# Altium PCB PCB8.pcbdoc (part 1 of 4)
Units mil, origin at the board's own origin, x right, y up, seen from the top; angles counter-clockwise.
Board outline 6799.06 x 5716.8 mil, 2 copper layers (Top Layer, Bottom Layer); 312 components, 374 nets, 1333 pads, 994 vias.
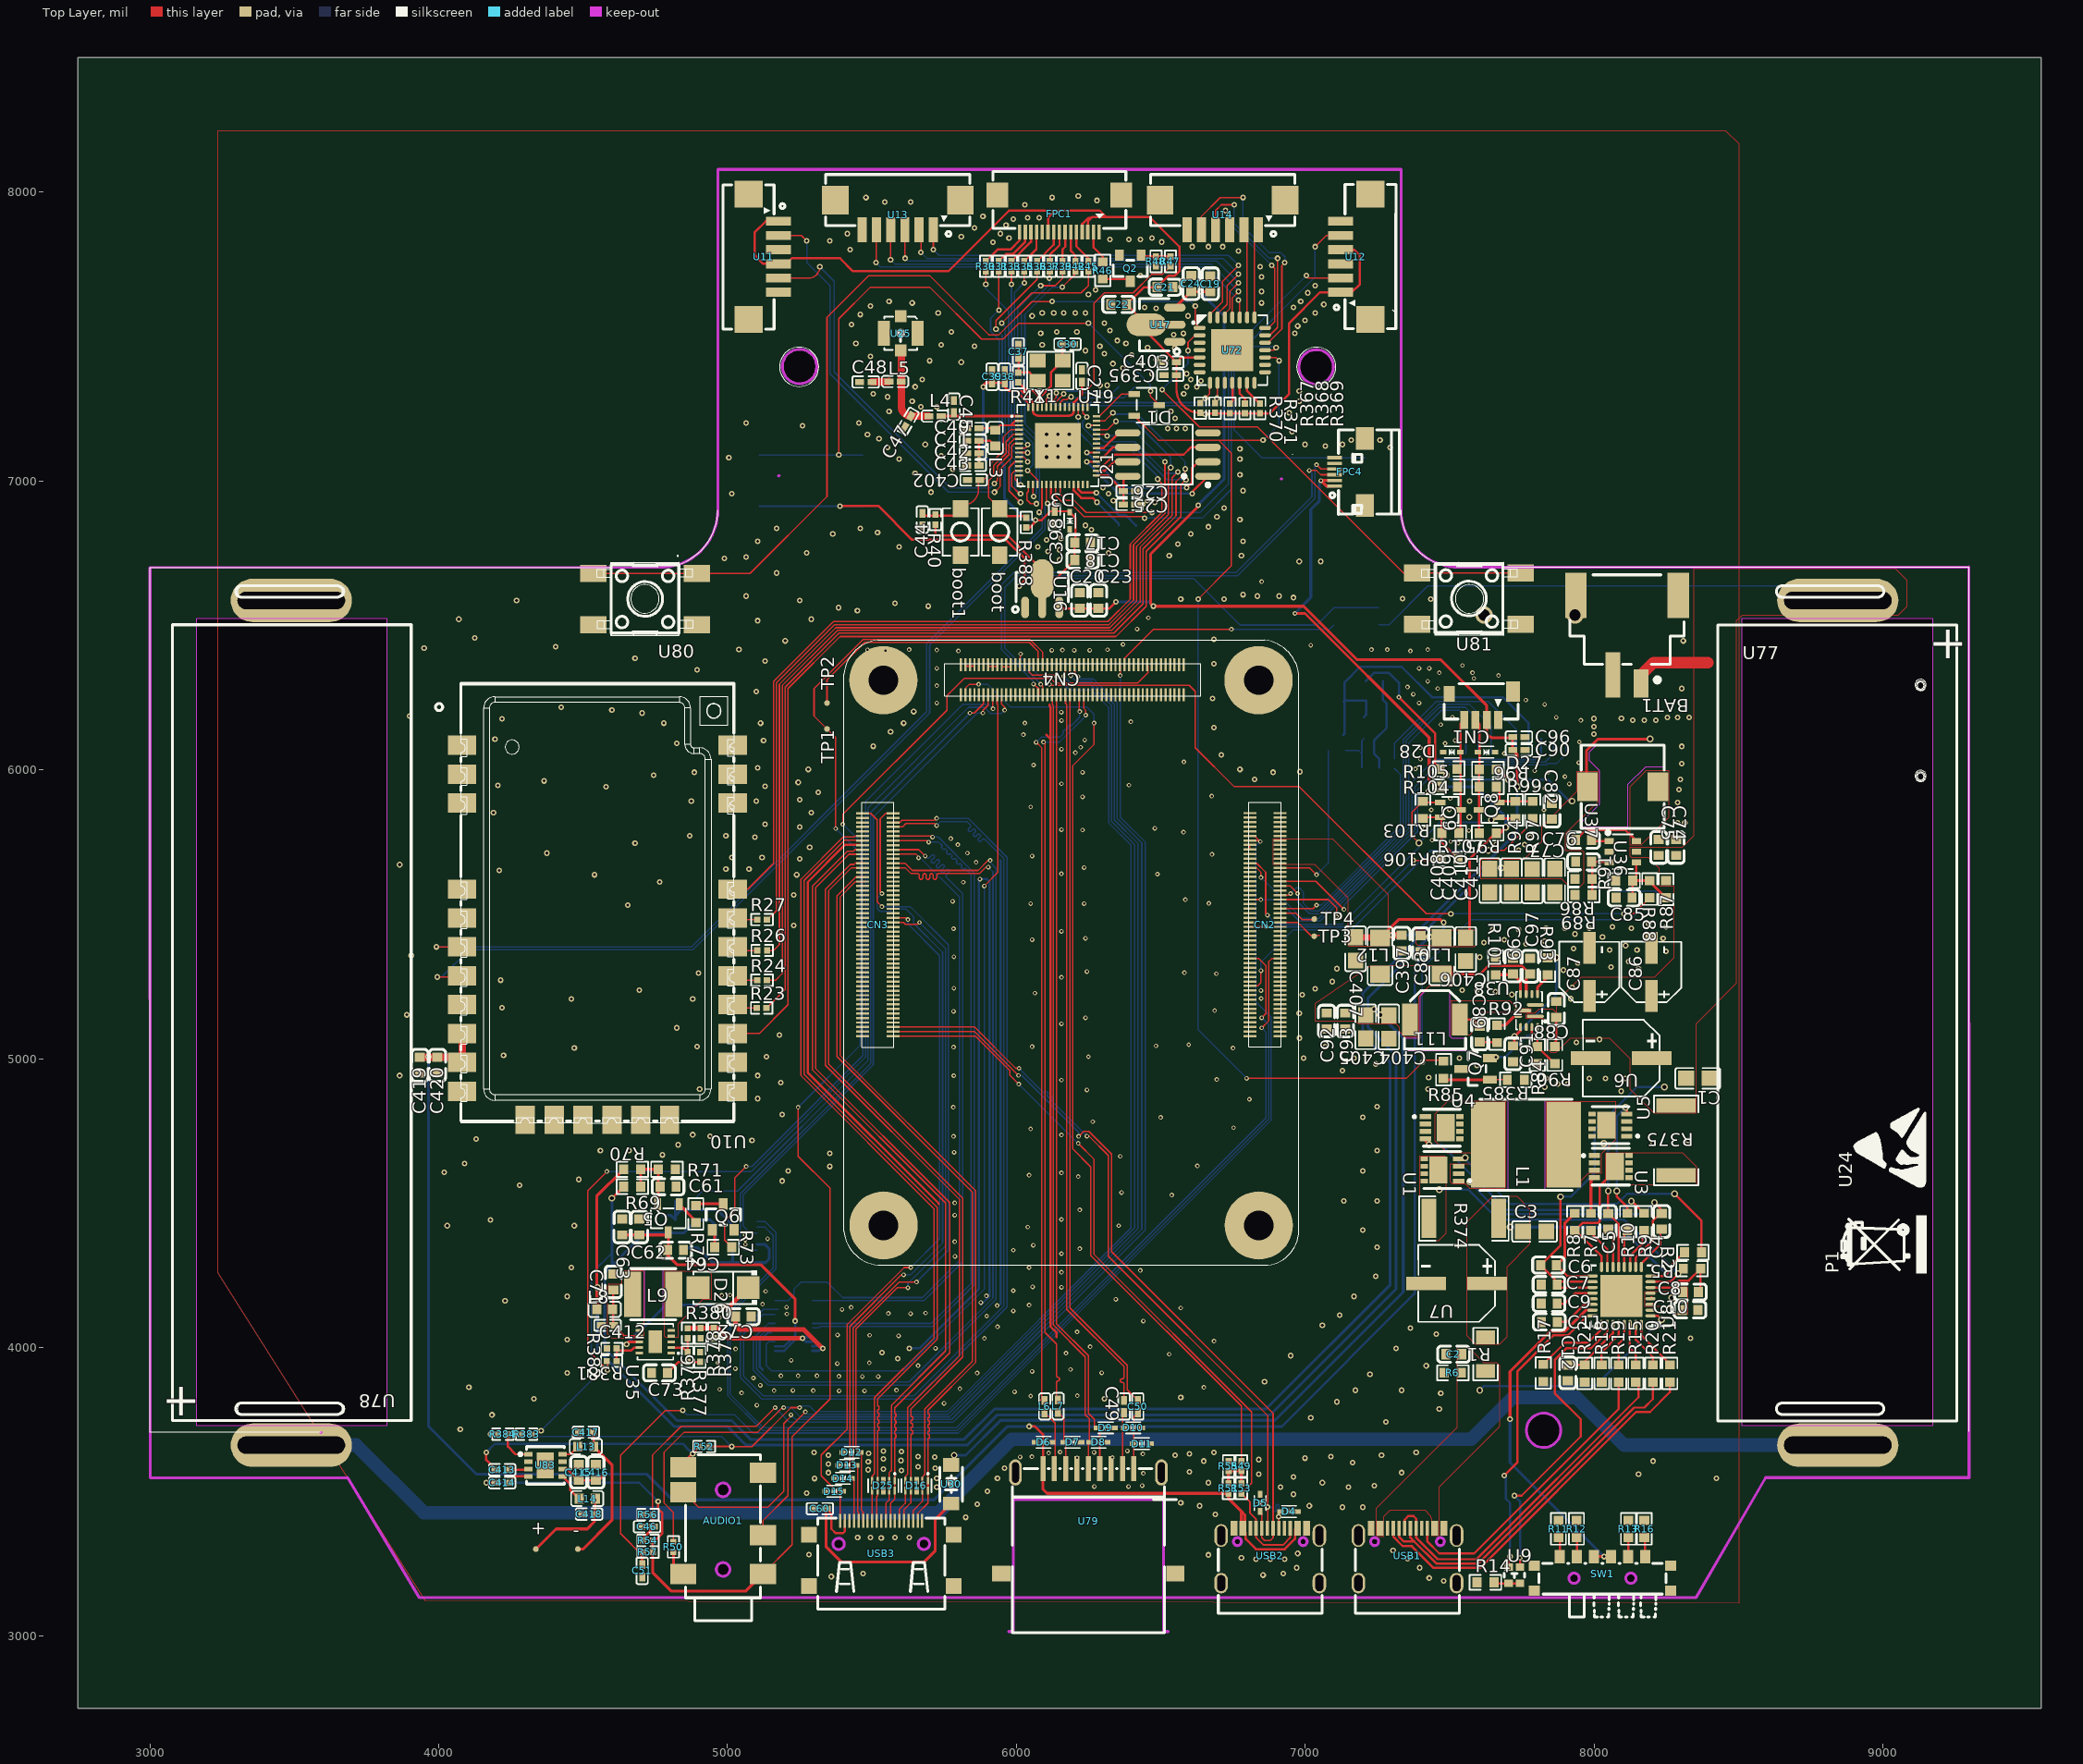
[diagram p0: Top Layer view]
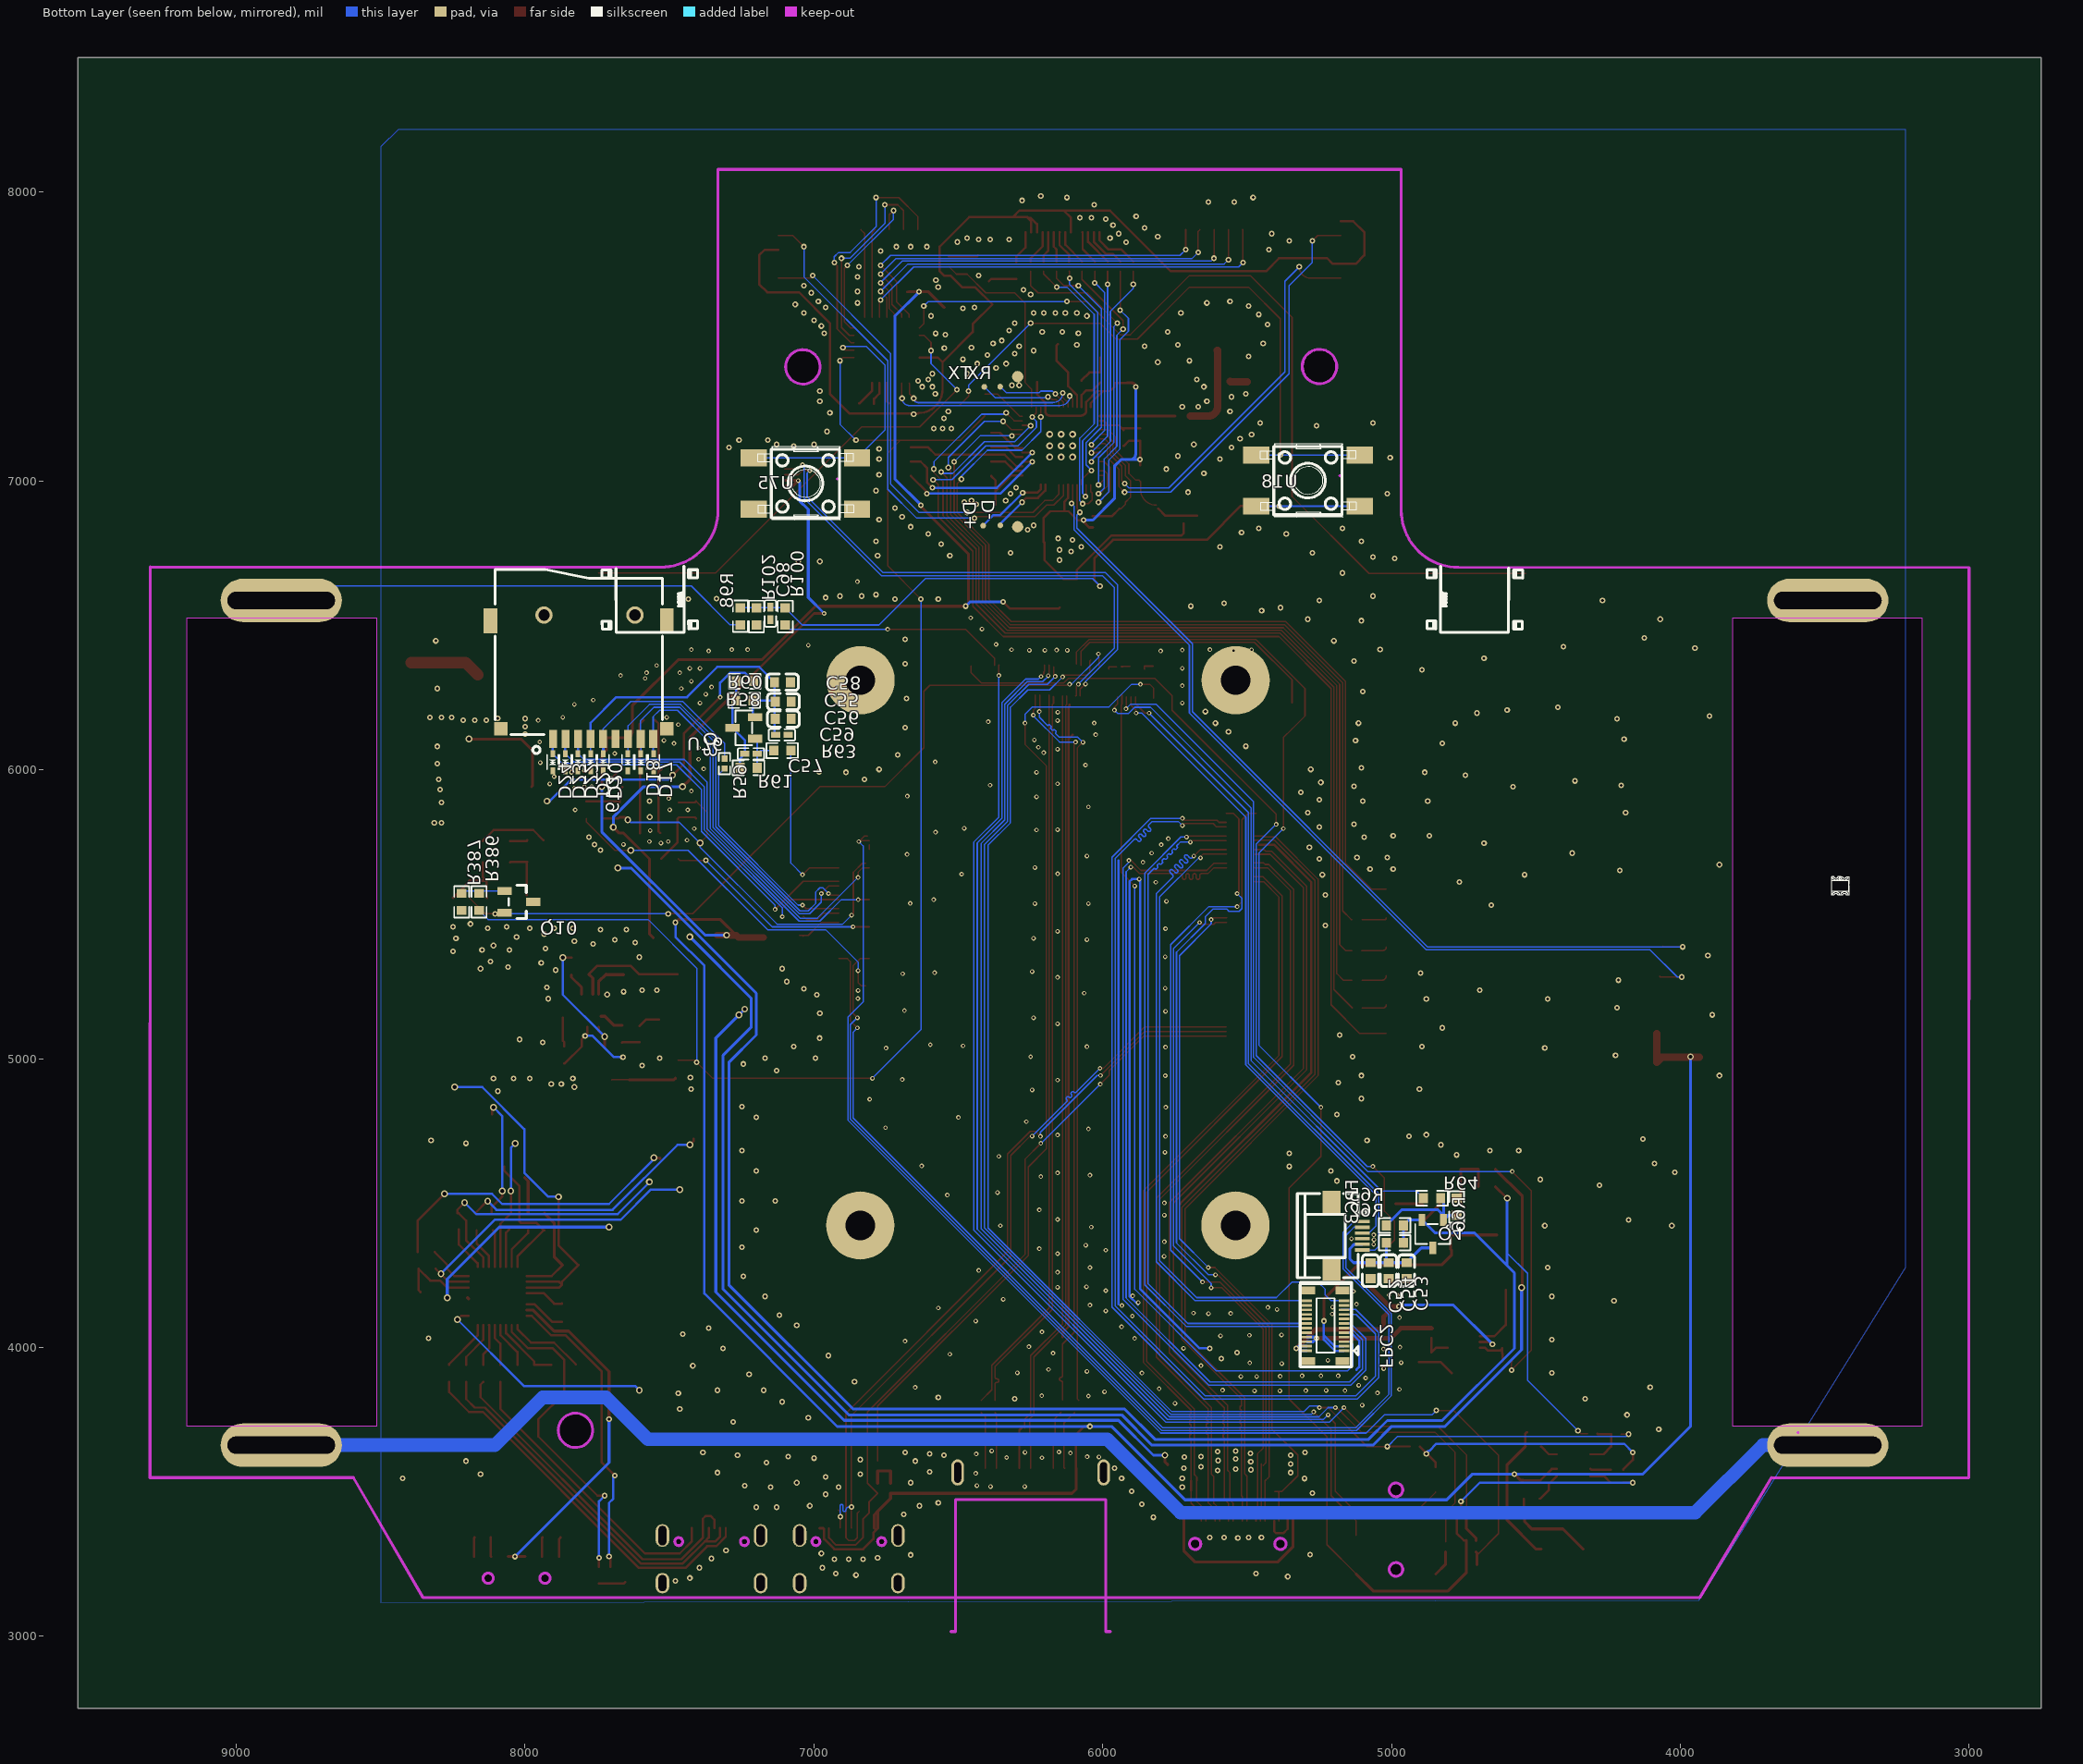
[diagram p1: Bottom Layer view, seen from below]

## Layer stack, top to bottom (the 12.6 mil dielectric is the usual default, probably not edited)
Top Layer: signal copper (thickness not stored)
Dielectric: dielectric 12.6, FR-4, Dk 4.8
Bottom Layer: signal copper (thickness not stored)

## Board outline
9549.06,2750 2750,2750 2750,8466.8 9549.06,8466.8
cut-out: 5309.02,7396.49 ccw(c5249.47,7396.49) 5189.91,7396.49 ccw(c5249.47,7396.49)
cut-out: 7097.89,7395.23 ccw(c7038.33,7395.03) 6978.78,7395.23 ccw(c7038.33,7395.44)
cut-out: 7885.29,3712.83 ccw(c7825.73,3712.63) 7766.18,3712.83 ccw(c7825.73,3713.03)
cut-out: 8513.52,6524.13 9172.18,6524.13 9172.18,3728.85 8513.52,3728.85
cut-out: 3161.75,6524.13 3820.41,6524.13 3820.41,3728.85 3161.75,3728.85

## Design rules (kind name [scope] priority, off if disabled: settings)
BoardOutlineClearance copperThickness1oz [All] p0: genericclearance=10 ignorepadtopadclearanceinfootprint=FALSE except(0: Arc-SplitContinuation Track-SplitContinuation SMDPad-SplitContinuation THPad-SplitContinuation Via-SplitContinuation Fill-SplitContinuation Poly-SplitContinuation Region-SplitContinuation Text-SplitContinuation; 6: Track-OutlineEdge SMDPad-OutlineEdge THPad-OutlineEdge Via-OutlineEdge Fill-OutlineEdge Region-OutlineEdge Poly-OutlineEdge Text-OutlineEdge Track-CutoutEdge SMDPad-CutoutEdge THPad-CutoutEdge Via-CutoutEdge Fill-CutoutEdge Region-CutoutEdge)
BoardOutlineClearance copperThickness2oz [All] p0: genericclearance=10 ignorepadtopadclearanceinfootprint=FALSE except(0: Arc-SplitContinuation Track-SplitContinuation SMDPad-SplitContinuation THPad-SplitContinuation Via-SplitContinuation Fill-SplitContinuation Poly-SplitContinuation Region-SplitContinuation Text-SplitContinuation; 6: Track-OutlineEdge SMDPad-OutlineEdge THPad-OutlineEdge Via-OutlineEdge Fill-OutlineEdge Region-OutlineEdge Poly-OutlineEdge Text-OutlineEdge Track-CutoutEdge SMDPad-CutoutEdge THPad-CutoutEdge Via-CutoutEdge Fill-CutoutEdge Region-CutoutEdge)
Clearance copperThickness1oz [(InNet('$1N1320') OR InNet('$1N1265') OR InNet('CHIP_PU') OR InNet('$1N1382') OR InNet('LY') OR InNet('LX') OR InNet('TOUCH_RST') OR InNet('INT') OR InNet('SCL') OR InNet('SDA') OR InNet('NX1') OR InNet('CS') OR InNet('MOSI') OR InNet('VDD3V3') OR InNet('RY') OR InNet('RX') OR InNet('USB_D-') OR InNet('USB_D+') OR InNet('VDD_SPI') OR InNet('SPIHD') OR InNet('SPIWP') OR InNet('SPICS0') OR InNet('SPICLK') OR InNet('SPIQ') OR InNet('SPID') OR InNet('SCK') OR InNet('MISO') OR InNet('DIO0') OR InNet('NSS') OR InNet('TXEN') OR InNet('RXEN') OR InNet('U0TX') OR InNet('U0RX') OR InNet('$1N1308') OR InNet('$1N1275') OR InNet('GND') OR InNet('$1N1307') OR InNet('$1N1322') OR InNet('$1N3518') OR InNet('3V3') OR InNet('$1N3038') OR InNet('$1N3048') OR InNet('$1N3058') OR InNet('$1N3068') OR InNet('$1N3078') OR InNet('$1N3252') OR InNet('$1N3231') OR InNet('$1N3221') OR InNet('$1N3208') OR InNet('$1N3517') OR InNet('$1N3432') OR InNet('BAT') OR InNet('MU-SCL') OR InNet('MU-SDA') OR InNet('$1N7464') OR InNet('$1N7325') OR InNet('+5V') OR InNet('$1N7323') OR InNet('$1N7321') OR InNet('VBUS') OR InNet('VBYSG') OR InNet('VBUSI') OR InNet('CSN1') OR InNet('PCIN') OR InNet('HG1') OR InNet('BST1') OR InNet('$1N9630') OR InNet('LG1') OR InNet('LG2') OR InNet('LX2') OR InNet('BST2') OR InNet('HG2') OR InNet('PCON') OR InNet('CSN2') OR InNet('$1N9623') OR InNet('$1N9626') OR InNet('RBAT') OR InNet('$1N9603') OR InNet('$1N9608') OR InNet('$1N9622') OR InNet('$1N9601') OR InNet('$1N9600') OR InNet('$1N9598') OR InNet('$1N9599') OR InNet('CC1') OR InNet('DM') OR InNet('DP') OR InNet('CC2') OR InNet('$1N9644') OR InNet('$1N9541') OR InNet('$1N9548') OR InNet('$1N9610') OR InNet('$1N9637') OR InNet('$1N9636') OR InNet('$1N9649') OR InNet('$1N9650') OR InNet('$1N9582') OR InNet('A0') OR InNet('B2') OR InNet('B1') OR InNet('B0') OR InNet('A1') OR InNet('A2') OR InNet('B5') OR InNet('B4') OR InNet('B3') OR InNet('A3') OR InNet('PA1') OR InNet('PA_ADC') OR InNet('$1N12616') OR InNet('$1N14613') OR InNet('$1N28296') OR InNet('$1N28297') OR InNet('$1N28298') OR InNet('A4') OR InNet('PWM3_IR') OR InNet('I2C2_SCL_M1') OR InNet('I2C2_SDA_M1') OR InNet('PMW0_M1') OR InNet('SDMMC0_CLK') OR InNet('SDMMC0_D3/ARMJTAG_TMS') OR InNet('SDMMC0_CMD') OR InNet('SDMMC0_D0') OR InNet('SDMMC0_D1') OR InNet('SDMMC0_D2/ARMJTAG_TCK') OR InNet('SDMMC_PWREN') OR InNet('SDMMC0_DET_L') OR InNet('GPIO_VREF') OR InNet('+1V8') OR InNet('USB_OTG0_ID') OR InNet('USB_OTG0_DM') OR InNet('USB_OTG0_DP') OR InNet('HDMI_TX1N_PORT') OR InNet('HDMI_TX_CEC_PORT') OR InNet('HDMI_TX_HPD_PORT') OR InNet('HDMI_TX2P_PORT') OR InNet('HDMI_TX2N_PORT') OR InNet('MIPI_DSI_TX1_D0N') OR InNet('HDMI_TX1P_PORT') OR InNet('MIPI_DSI_TX1_D0P') OR InNet('MIPI_DSI_TX1_D1N') OR InNet('HDMI_TX0P_PORT') OR InNet('MIPI_DSI_TX1_D1P') OR InNet('HDMI_TX0N_PORT') OR InNet('MIPI_DSI_TX1_CLKN') OR InNet('HDMI_TXCLKP_PORT') OR InNet('MIPI_DSI_TX1_CLKP') OR InNet('HDMI_TXCLKN_PORT') OR InNet('MIPI_DSI_TX1_D2N') OR InNet('MIPI_DSI_TX1_D2P') OR InNet('HDMI_TXDDC_SDA_PORT') OR InNet('HDMI_TXDDC_SCL_PORT') OR InNet('SARADC_VIN1_HW_ID') OR InNet('SARADC_VIN2_HP_HOOK') OR InNet('USB3_HOST1_DP') OR InNet('USB3_HOST1_DM') OR InNet('HPL_OUT') OR InNet('HP_SNS') OR InNet('HPR_OUT') OR InNet('MIC1_IN') OR InNet('MIC2_IN') OR InNet('3V3_PWR_EN') OR InNet('TP_DET_1') OR InNet('MIPI_BL_EN_1') OR InNet('TP_INT_1') OR InNet('TP_RST_1') OR InNet('USB_OTG0_VBUSDET') OR InNet('VCCIO_SD') OR InNet('VCC3V3_SD_1') OR InNet('$3N6200') OR InNet('VCC3V3_SYS') OR InNet('$3N7118') OR InNet('$3N8858') OR InNet('$3N10292') OR InNet('$3N10242') OR InNet('$3N10406') OR InNet('$3N10376') OR InNet('$3N10139') OR InNet('$3N11471') OR InNet('$3N11421') OR InNet('$3N11399') OR InNet('VCC_LEDA1') OR InNet('$3N11460') OR InNet('$3N11495') OR InNet('MIPI_LCD_BL_') OR InNet('VCC_LEDK1') OR InNet('VCC5V0_USB') OR InNet('$3N12575') OR InNet('$3N12564') OR InNet('$3N12560') OR InNet('$3N12532') OR InNet('$3N12811') OR InNet('VCC_TP') OR InNet('VCC_LCD_MIPI') OR InNet('$3N29784') OR InNet('VCC') OR InNet('$3N24558') OR InNet('$3N24551') OR InNet('$3N24908') OR InNet('+5V_INPUT') OR InNet('$3N24693') OR InNet('$3N24554') OR InNet('VCC_LDO5V') OR InNet('$3N25630') OR InNet('$3N25659') OR InNet('$3N25599') OR InNet('$3N25641') OR InNet('$3N26750') OR InNet('$3N29756') OR InNet('$3N30068') OR InNet('$3N31158') OR InNet('$3N30821') OR InNet('$3N31177') OR InNet('$1N4606') OR InNet('$1N1392') OR InNet('LEDA1') OR InNet('$3N38895') OR InNet('A5') OR InNet('A6') OR InNet('MIPI_RESET_1') OR InNet('HP_DET_L_GPIO4_C4') OR InNet('USB3_HOST1_SSRXN') OR InNet('USB3_HOST1_SSRXP') OR InNet('USB3_HOST1_SSTXN') OR InNet('USB3_HOST1_SSTXP') OR InNet('MIPI_LCD_EN_1') OR InNet('UART2_TX') OR InNet('UART2_RX') OR InNet('HPL') OR InNet('HPR') OR InNet('$1N43466') OR InNet('$1N42754') OR InNet('$1N42758') OR InNet('$1N42976') OR InNet('$1N42978') OR InNet('$1N43424') OR InNet('$1N43427') OR InNet('RST1') OR InNet('DC1') OR InNet('CS1') OR InNet('MOSI1') OR InNet('SCLK1') OR InNet('$1N7607') OR InNet('$1N7610') OR InNet('$1N9627') OR InNet('$1N9602') OR InNet('$1N56076') OR InNet('$1N56079') OR InNet('OFF') OR InNet('$3N65029') OR InNet('CAM_PWR_2') OR InNet('I2C3_SDA_TP') OR InNet('5V_PWR_EN') OR InNet('I2C3_SCL_TP') OR InNet('MIPI_LCD_EN_2') OR InNet('TP_RST_L') OR InNet('LCD1_PWREN_H') OR InNet('TP_INT_L') OR InNet('CAM_RESET_1') OR InNet('BAT_3V7_LOSE') OR InNet('USB_PWR_H') OR InNet('TP_PWR_DET') OR InNet('PCIE20_WAKEN') OR InNet('SARADC_VIN0_KEY/RECOVERY') OR InNet('MIPI_LCD_BL_1') OR InNet('USB2.0_HUB_PWR') OR InNet('TS') OR InNet('BAT_3V7_PLUS') OR InNet('SPKN_OUT') OR InNet('SPKP_OUT') OR InNet('MIPI_DSI_TX0_D2P/LVDS_TX0_D2P') OR InNet('EDP_TX_D3P') OR InNet('MIPI_DSI_TX0_D3N/LVDS_TX0_D3N') OR InNet('EDP_TX_D2N') OR InNet('MIPI_DSI_TX0_D2N/LVDS_TX0_D2N') OR InNet('USB2_HOST2_DP') OR InNet('EDP_TX_D3N') OR InNet('MIPI_DSI_TX0_D3P/LVDS_TX0_D3P') OR InNet('EDP_TX_D2P') OR InNet('USB2_HOST2_DM') OR InNet('MIPI_LCD_BL_2') OR InNet('EDP_TX_D0N') OR InNet('EDP_TX_AUXP') OR InNet('MIPI_RESET_2') OR InNet('EDP_TX_D0P') OR InNet('EDP_TX_D1N') OR InNet('LCD0_BL_PWM5') OR InNet('EDP_TX_AUXN') OR InNet('USB2_HOST3_DP') OR InNet('EDP_TX_D1P') OR InNet('MIPI_BL_EN_2') OR InNet('USB2_HOST3_DM') OR InNet('LCD0_BL_EN') OR InNet('$3N5478') OR InNet('+3.3V') OR InNet('PCIE20_CLKREQN_M2') OR InNet('PCIE20_TXP') OR InNet('PCIE20_RXN') OR InNet('PCIE20_RXP') OR InNet('PCIE20_REFCLKP') OR InNet('PCIE20_REFCLKN') OR InNet('PCIE20_TXN') OR InNet('MIPI_DSI_TX1_D3N') OR InNet('MIPI_DSI_TX1_D3P') OR InNet('MIPI_CSI_RX_D2N') OR InNet('MIPI_CSI_RX_D2P') OR InNet('MIPI_CSI_RX_D3N') OR InNet('MIPI_CSI_RX_D3P') OR InNet('MIPI_CSI_RX_CLK1P') OR InNet('MIPI_CSI_RX_CLK1N') OR InNet('MIPI_DSI_TX0_CLKN/LVDS_TX0_CLKN') OR InNet('TV_OUT') OR InNet('MIPI_DSI_TX0_CLKP/LVDS_TX0_CLKP') OR InNet('MIPI_CSI_RX_D0N') OR InNet('PCIE_NRST') OR InNet('MIPI_CSI_RX_D0P') OR InNet('MIPI_CSI_RX_D1N') OR InNet('MIPI_CSI_RX_D1P') OR InNet('MIPI_DSI_TX0_D1P/LVDS_TX0_D1P') OR InNet('MIPI_DSI_TX0_D1N/LVDS_TX0_D1N') OR InNet('MIPI_CSI_RX_CLK0P') OR InNet('MIPI_DSI_TX0_D0P/LVDS_TX0_D0P') OR InNet('MIPI_CSI_RX_CLK0N') OR InNet('MIPI_DSI_TX0_D0N/LVDS_TX0_D0N') OR InNet('PHY1_MDI1+') OR InNet('EEPROM_NWP') OR InNet('PHY1_MDI1-') OR InNet('SYNC_OUT') OR InNet('SYNC_IN') OR InNet('PHY1_MDI0-') OR InNet('PHY1_MDI0+') OR InNet('I2C2_SCL_MO') OR InNet('I2S1_SDI3_M1') OR InNet('I2C2_SDA_MO') OR InNet('PMW0_M0') OR InNet('PMIC_RESET_KEY') OR InNet('I2S1_LRCK_TX_M1') OR InNet('RUN_PG') OR InNet('AIN1') OR InNet('AIN0') OR InNet('SPI0_CSO_MO') OR InNet('I2C0_SDA_PMIC') OR InNet('SPI0_MISO_MO') OR InNet('I2C0_SCL_PMIC') OR InNet('I2S1_SDO2_M1') OR InNet('PMW4') OR InNet('SPI3_MOSI_M0') OR InNet('SPI3_CLK_M0') OR InNet('SPI3_MISO_M0') OR InNet('SARADC_IN3') OR InNet('PWRON_KEY') OR InNet('CAM_GPIO') OR InNet('NPWR_LED') OR InNet('NRPIBOOT') OR InNet('BT_NDIS') OR InNet('I2S1_MCLK_M1') OR InNet('PHY1_MDI2+') OR InNet('PHY1_LED2_Y') OR InNet('SPI3_CSO_M0') OR InNet('WL_NDIS') OR InNet('PHY1_MDI2-') OR InNet('PHY1_LED1_G') OR InNet('PHY1_LED0_Y1') OR InNet('PHY1_MDI3-') OR InNet('PI_NLED_ACTIVITY') OR InNet('I2S1_SDI1_M1') OR InNet('PHY1_MDI3+') OR InNet('I2S1_SDO0_M1') OR InNet('I2S1_SDI2_M1') OR InNet('I2S1_SCLK_TX_M1') OR InNet('PWM11') OR InNet('I2S1_LRCK_RX_M1') OR InNet('I2S1_SDI0_M1') OR InNet('$3N5591'))] p1: gap=7 ignorepadtopadclearanceinfootprint=FALSE except(4: Track-Track; 6: Track-SMDPad SMDPad-SMDPad Track-THPad SMDPad-THPad THPad-THPad Track-Via SMDPad-Via THPad-Via Via-Via Track-Fill SMDPad-Fill THPad-Fill Via-Fill Fill-Fill Track-Region SMDPad-Region THPad-Region Via-Region Fill-Region Region-Region Track-Poly SMDPad-Poly THPad-Poly Via-Poly Fill-Poly Region-Poly Poly-Poly Track-Text SMDPad-Text THPad-Text Via-Text Fill-Text Region-Text Poly-Text Text-Text Track-Sheet SMDPad-Sheet THPad-Sheet Via-Sheet Fill-Sheet Region-Sheet Poly-Sheet Text-Sheet Track-Hole SMDPad-Hole THPad-Hole Via-Hole Fill-Hole Region-Hole Poly-Hole Text-Hole Sheet-Hole)
Clearance copperThickness2oz [All] p1: gap=7 ignorepadtopadclearanceinfootprint=FALSE except(6: Track-SMDPad SMDPad-SMDPad Track-THPad SMDPad-THPad THPad-THPad Track-Via SMDPad-Via THPad-Via Via-Via Track-Fill SMDPad-Fill THPad-Fill Via-Fill Fill-Fill Track-Region SMDPad-Region THPad-Region Via-Region Fill-Region Region-Region Track-Poly SMDPad-Poly THPad-Poly Via-Poly Fill-Poly Region-Poly Poly-Poly Track-Text SMDPad-Text THPad-Text Via-Text Fill-Text Region-Text Poly-Text Text-Text Track-Sheet SMDPad-Sheet THPad-Sheet Via-Sheet Fill-Sheet Region-Sheet Poly-Sheet Text-Sheet Track-Hole SMDPad-Hole THPad-Hole Via-Hole Fill-Hole Region-Hole Poly-Hole Text-Hole Sheet-Hole; 8: Track-Track)
DiffPairsRouting differentialPair [All] p1: maxuncoupledlength=10 minlimit=5.9843 maxlimit=5.9843 mostfreqgap=5.9843 toplayer_minwidth=5 toplayer_prefwidth=10 toplayer_maxwidth=100 bottomlayer_minwidth=5 bottomlayer_prefwidth=10 bottomlayer_maxwidth=100
PasteMaskExpansion pasteMaskExpansion [All] p1: expansion=0
PlaneConnect innerPlane [All] p1: planeconnectstyle=Relief reliefexpansion=20 reliefentries=4 reliefconductorwidth=10 reliefairgap=10
PolygonConnect copperRegion [All] p1: connectstyle=Direct reliefentries=4 reliefconductorwidth=10 polygonreliefangle="90 Angle" airgapwidth=10
RoutingVias viaSize [All] p1: viastyle="Through Hole" holewidth=12 minholewidth=7.874 maxholewidth=248 width=24 minwidth=15.748 maxwidth=393.7
SolderMaskExpansion solderMaskExpansion [All] p1: useseparateexpansions=TRUE expansion=2.0079 expansionbottom=2.0079
Width copperThickness1oz [All] p1: maxlimit=100 minlimit=5 preferedwidth=10
Width copperThickness2oz [All] p1: maxlimit=100 minlimit=8 preferedwidth=10

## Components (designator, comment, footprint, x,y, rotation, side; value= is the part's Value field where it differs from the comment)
+ "Test-Point" Test-Point-0.5mm 4336.15,3301.41 r0 top
- "Test-Point" Test-Point-0.5mm 4481.78,3301.41 r0 top
AUDIO1 "PJ-3420-A-SMT" AUDIO-SMD_PJ-3420-A-SMT_C319102 4984.47,3400.45 r90 top
BAT1 "XH2.54-2P" CONN-SMD_2P-P2.50-WT 8114.47,6466.49 r180 top
boot "Key_SMD_3x4x2" Key_SMD_3x4x2 5942.18,6823.81 r270 top
boot1 "Key_SMD_3x4x2" Key_SMD_3x4x2 5807.18,6823.81 r270 top
C1 "CAP_0805" C0805 8359.47,4931.49 r180 top
C2 "CAP_0603" C0603 7514.47,3976.49 r0 top
C3 "CAP_0805" C0805 7794.47,4401.49 r180 top
C4 "CAP_0603" C0603 8234.47,4436.49 r90 top
C5 "CAP_0603" C0603 8049.47,4436.49 r90 top
C6 "CAP_0603" C0603 7843.02,4284.87 r0 top
C7 "CAP_0603" C0603 7844.91,4217 r0 top
C8 "CAP_0603" C0603 8334.47,4191.49 r0 top
C9 "CAP_0603" C0603 7844.91,4152.26 r0 top
C10 "CAP_0603" C0603 8333.02,4129.87 r0 top
C11 "CAP_0603" C0603 7845.72,4087.77 r0 top
C12 "CAP_0603" C0603 7909.47,3911.49 r270 top
C17 "CAP_0603" C0603 6229.47,6786.49 r180 top
C18 "CAP_0603" C0603 6229.47,6726.49 r180 top
C19 "CAP_0603" C0603 6671.76,7682.65 r270 top
C20 "CAP_0603" C0603 6219.47,6586.49 r270 top
C21 "CAP_0603" C0603 6514.47,7671.49 r180 top
C22 "CAP_0603" C0603 6354.47,7611.49 r0 top
C23 "CAP_0603" C0603 6284.47,6586.49 r270 top
C24 "CAP_0603" C0603 6605.41,7683.59 r270 top
C25 "CAP_0402" C0402 6392.18,6918.81 r180 top
C26 "CAP_0402" C0402 6392.02,6964.72 r180 top
C27 "CAP_0402" C0402 6227.18,7363.81 r270 top
C30 "CAP_0402" C0402 6177.18,7473.81 r0 top
C37 "CAP_0402" C0402 6007.18,7448.81 r270 top
C38 "CAP_0402" C0402 5959.6,7361.23 r270 top
C39 "CAP_0402" C0402 5916.02,7361.23 r270 top
C40 "CAP_0402" C0402 5849.27,7182.34 r0 top
C41 "CAP_0402" C0402 5849.27,7139.5 r0 top
C42 "CAP_0402" C0402 5849.27,7096.65 r0 top
C43 "CAP_0402" C0402 5849.27,7053.81 r0 top
C44 "CAP_0402" C0402 5674.47,6866.49 r90 top
C45 "CAP_0402" C0402 5783.55,7257.59 r270 top
C46 "CAP_0402" C0402 4721.19,3378.86 r0 top
C47 "CAP_0402" C0402 5624.47,7206.49 r60 top
C48 "CAP_0402" C0402 5478.55,7343.21 r0 top
C49 "CAP_0402" C0402 6372.65,3795.32 r270 top
C50 "CAP_0402" C0402 6420.36,3795.32 r270 top
C51 "CAP_0402" C0402 4704.47,3226.49 r90 top
C52 "CAP_0603" C0603 5072.91,4265.79 r90 bottom
C53 "CAP_0603" C0603 4947.72,4265.79 r90 bottom
C54 "CAP_0603" C0603 5010.31,4265.79 r90 bottom
C55 "CAP_0603" C0603 7106.03,6236.21 r0 bottom
C56 "CAP_0603" C0603 7106.03,6176.21 r0 bottom
C57 "CAP_0402" C0402 7217.85,6055.26 r0 bottom
C58 "CAP_0603" C0603 7108.97,6303.53 r0 bottom
C59 "CAP_0402" C0402 7110.83,6120.8 r0 bottom
C60 "CAP_0402" C0402 5319.47,3441.49 r0 top
C61 "CAP_0603" C0603 4794.28,4556.19 r0 top
C62 "CAP_0603" C0603 4695.01,4416.8 r270 top
C63 "CAP_0603" C0603 4635.01,4416.8 r270 top
C64 "CAP_0603" C0603 4820.01,4336.8 r180 top
C71 "CAP_0603" C0603 4604.47,4226.49 r270 top
C72 "CAP_0603" C0603 5054.47,4106.49 r180 top
C73 "CAP_0603" C0603 4764.47,3911.49 r0 top
C74 "CAP_0603" C0603 8284.26,5730.88 r270 top
C75 "CAP_0603" C0603 8224.26,5730.88 r270 top
C76 "CAP_0603" C0603 7964.47,5756.49 r0 top
C77 "CAP_0603" C0603 7964.47,5681.49 r0 top
C82 "CAP_0603" C0603 7854.47,5856.49 r270 top
C83 "CAP_0603" C0603 7400.27,5398.06 r90 top
C85 "CAP_0603" C0603 8104.47,5556.49 r0 top
C86 "CS22UF35V5*5.4" CAP-SMD_BD5.0-L5.3-W5.3-LS6.0-FD 8199.43,5300.04 r90 top
C87 "CS22UF35V5*5.4" CAP-SMD_BD5.0-L5.3-W5.3-LS6.0-FD 7984.43,5300.04 r90 top
C88 "CAP_0603" C0603 7869.43,5170.04 r270 top
C89 "CAP_0603" C0603 7604.43,5085.04 r270 top
C90 "CAP_0402" C0402 7740.26,6068.7 r0 top
C91 "CAP_0603" C0603 7719.47,5016.49 r90 top
C92 "CAP_0603" C0603 7074.43,5130.04 r90 top
C93 "CAP_0603" C0603 7139.43,5130.04 r90 top
C96 "CAP_0402" C0402 7740.26,6113.7 r0 top
C97 "CAP_0603" C0603 7779.43,5320.04 r90 top
C98 "CAP_0402" C0402 7150.64,6541.36 r90 bottom
C99 "CAP_0603" C0603 7719.43,5320.04 r270 top
C395 "CAP_0402" C0402 6533.07,7366.46 r0 top
C397 "CAP_0603" C0603 7334.43,5400.04 r90 top
C398 "CAP_0402" C0402 6132.18,6873.81 r90 top
C402 "CAP_0402" C0402 5852.18,7003.81 r180 top
C403 "CAP_0402" C0402 6533.07,7411.46 r0 top
C404 "CAP_0805" C0805 7289.76,5109.5 r90 top
C405 "CAP_0805" C0805 7209.43,5110.04 r90 top
C406 "CAP_0805" C0805 7556.27,5378.29 r270 top
C407 "CAP_0805" C0805 7174.43,5380.04 r270 top
C408 "CAP_0805" C0805 7639.47,5616.49 r90 top
C409 "CAP_0805" C0805 7714.47,5616.49 r90 top
C410 "CAP_0805" C0805 7786.6,5615.71 r90 top
C411 "CAP_0805" C0805 7864.47,5616.49 r90 top
C412 "CAP_0402" C0402 4584.47,4076.49 r0 top
C413 "CAP_0402" C0402 4219.47,3576.49 r0 top
C414 "CAP_0402" C0402 4219.47,3531.49 r0 top
C415 "CAP_0603" C0603 4484.47,3567.15 r270 top
C416 "CAP_0603" C0603 4544,3567.15 r270 top
C417 "CAP_0402" C0402 4509.47,3706.49 r180 top
C418 "CAP_0402" C0402 4520.61,3422.78 r180 top
C419 "CAP_0603" C0603 3934.73,4977.1 r90 top
C420 "CAP_0603" C0603 3995.54,4977.1 r90 top
CN1 "W10001-104MSNER1" CONN-SMD_4P-P1.00_TXGA_FWF10002-S04S24W5M 7609.47,6221.49 r180 top
CN2 "DF40HC(3.0)-100DS-0.4V(58)" conn-smd_df40hc-3.0-100ds-0.4v-51#1 6866.24,5495.43 r270 top locked
CN3 "DF40HC(3.0)-100DS-0.4V(58)" CONN-SMD_DF40HC-3.0-100DS-0.4V-51 5522.93,5486.72 r270 top locked
CN4 "DF40HC(3.0)-100DS-0.4V(58)" conn-smd_df40hc-3.0-100ds-0.4v-51#2 6206.12,6309.76 r180 top locked
D1 "BAT54A,215" SOT-23-3_L3.0-W1.7-P0.95-LS2.9-BR 6451.11,7263.13 r180 top
D3 "ESD5Z5V0C_C129211" SOD-523_L1.2-W0.8-LS1.6-BI 6185.27,6862.44 r90 top
D4 "TVS" SOD-523_L1.2-W0.8-LS1.6-BI 6944.47,3431.49 r180 top
D5 "TVS" SOD-523_L1.2-W0.8-LS1.6-BI 6844.47,3461.49 r270 top
D6 "TVS" SOD-523_L1.2-W0.8-LS1.6-BI 6094.47,3671.49 r0 top
D7 "TVS" SOD-523_L1.2-W0.8-LS1.6-BI 6194.47,3671.49 r180 top
D8 "TVS" SOD-523_L1.2-W0.8-LS1.6-BI 6284.47,3671.49 r180 top
D9 "TVS" SOD-523_L1.2-W0.8-LS1.6-BI 6309.47,3721.49 r180 top
D10 "TVS" SOD-523_L1.2-W0.8-LS1.6-BI 6404.47,3721.49 r180 top
D11 "TVS" SOD-523_L1.2-W0.8-LS1.6-BI 6434.47,3666.49 r180 top
D12 "TVS" SOD-523_L1.2-W0.8-LS1.6-BI 5429.54,3636.49 r0 top
D13 "TVS" SOD-523_L1.2-W0.8-LS1.6-BI 5414.47,3591.49 r0 top
D14 "TVS" SOD-523_L1.2-W0.8-LS1.6-BI 5399.47,3546.49 r0 top
D15 "TVS" SOD-523_L1.2-W0.8-LS1.6-BI 5369.47,3501.49 r0 top
D16 "ESD5344D" DFN2510-10_L2.5-W1.0-P0.50-BL 5654.47,3521.49 r180 top
D17 "TVS" SOD-523_L1.2-W0.8-LS1.6-BI 7554.47,6026.49 r90 bottom
D18 "TVS" SOD-523_L1.2-W0.8-LS1.6-BI 7599.47,6026.49 r90 bottom
D19 "TVS" SOD-523_L1.2-W0.8-LS1.6-BI 7644.47,6026.49 r90 bottom
D20 "TVS" SOD-523_L1.2-W0.8-LS1.6-BI 7729.47,6026.49 r90 bottom
D21 "TVS" SOD-523_L1.2-W0.8-LS1.6-BI 7773.22,6026.49 r90 bottom
D22 "TVS" SOD-523_L1.2-W0.8-LS1.6-BI 7816.97,6026.49 r90 bottom
D23 "TVS" SOD-523_L1.2-W0.8-LS1.6-BI 7860.72,6026.49 r90 bottom
D24 "TVS" SOD-523_L1.2-W0.8-LS1.6-BI 7904.47,6026.49 r90 bottom
D25 "ESD5344D" DFN2510-10_L2.5-W1.0-P0.50-BL 5539.47,3521.49 r180 top
D26 "SS34_C8678" SMA_L4.3-W2.6-LS5.2-RD 4984.47,4206.49 r180 top
D27 "TVS" SOD-523_L1.2-W0.8-LS1.6-BI 7627.76,6061.2 r0 top
D28 "TVS" SOD-523_L1.2-W0.8-LS1.6-BI 7507.76,6061.2 r180 top
D+ "Test-Point" test-point-0.5mm 6414.21,6845.41 r90 bottom
D- "Test-Point" Test-Point-0.5mm 6354.47,6846.49 r180 bottom
FPC1 "GT-F0512SR18-15S0101" FPC-SMD_15P-P0.50_GT-F0512SR18-15S0101 6149.01,7925.82 r180 top
FPC2 "OK-06F024-04" OK-06F024-04 5164.47,4161.49 r90 bottom
FPC3 "AFC01-S06FCA-00" FPC-SMD_P0.50-6P_AFC01-S06FCA-00 5154.47,4386.49 r270 bottom
FPC4 "AFC01-S06FCA-00" FPC-SMD_P0.50-6P_AFC01-S06FCA-00 7154.47,7031.49 r90 top
L1 "NR8040T330M" IND-SMD_L8.0-W8.0 7764.47,4701.49 r180 top
L3 "L_0603" L0603 5927.18,7148.81 r270 top
L4 "L_0402" L0402 5718.55,7224.67 r0 top
L5 "L_0402" L0402 5580.01,7344.67 r180 top
L6 "L_0402" L0402 6098.07,3795.32 r270 top
L7 "L_0402" L0402 6144.47,3796.49 r270 top
L8 "L_0603" L0603 4574.47,4131.49 r0 top
L9 "SWPA4020S4R7MT" IND-SMD_L4.0-W4.0_LQH44PN2R2MP0L 4742.64,4184.11 r0 top
L10 "L_1206" L1206 7472.83,5355.62 r90 top
L11 "SPM5020T-2R2M-LR" IND-SMD_L5.4-W5.1_SPM5020 7449.43,5135.04 r180 top
L12 "L_1206" L1206 7259.43,5355.04 r90 top
L13 "L_0603" L0603 4509.47,3656.49 r0 top
L14 "L_0603" L0603 4514.47,3476.15 r0 top
P1 "回收和循环利用" "垃圾桶LOGO COPY" 8974.47,4351.49 r90 top
Q2 "S8050_SOT_NPN" S8050_SOT-23 6399.47,7736.49 r90 top
Q3 "WPM2301-3/TR" SOT-23-3_L2.9-W1.3-P1.90-LS2.4-BR 7242.85,6145.26 r180 bottom
Q4 "WPM2015-3/TR" SOT-23-3_L2.9-W1.6-P1.90-LS2.8-BR 4857.2,4393.11 r90 bottom
Q5 "WPM2015-3/TR" SOT-23-3_L2.9-W1.6-P1.90-LS2.8-BR 4795.01,4446.8 r90 top
Q6 "S8050_SOT_NPN" S8050_SOT-23 4980.01,4451.8 r270 top
Q7 "S8550_SOT_PNP" S8550P_SOT 7589,4964.35 r0 top
Q8 "2SK3018FPDT106" SOT-323-3_L2.0-W1.3-P1.30-LS2.1-BR 7637.76,5861.2 r0 top
Q9 "2SK3018FPDT106" SOT-323-3_L2.0-W1.3-P1.30-LS2.1-BR 7502.76,5861.2 r180 top
Q10 "S8550_SOT_PNP" S8550P_SOT 8019.79,5542.68 r0 bottom
R1 "Res_1206" R1206 7624.47,3976.49 r90 top
R2 "Res_0603" R0603 8342.68,4329.53 r180 top
R5 "Res_0603" R0603 8339.39,4272.06 r180 top
R6 "Res_0603" R0603 7511.49,3911.88 r0 top
R7 "Res_0603" R0603 7989.68,4434.87 r90 top
R8 "Res_0603" R0603 7933.02,4434.87 r270 top
R9 "Res_0603" R0603 8173.02,4434.87 r90 top
R10 "Res_0603" R0603 8116.35,4434.87 r90 top
R11 "Res_0603" R0603 7876.97,3371.49 r270 top
R12 "Res_0603" R0603 7939.47,3371.49 r90 top
R13 "Res_0603" R0603 8119.47,3371.49 r90 top
R14 "Res_0603" R0603 7624.47,3186.49 r0 top
R15 "Res_0603" R0603 8027.02,3909.87 r90 top
R16 "Res_0603" R0603 8174.47,3371.49 r90 top
R17 "Res_0603" R0603 7824.47,3911.49 r90 top
R18 "Res_0603" R0603 8086.02,3909.87 r90 top
R19 "Res_0603" R0603 8145.02,3909.87 r90 top
R20 "Res_0603" R0603 8204.02,3909.87 r90 top
R21 "Res_0603" R0603 8263.02,3909.87 r90 top
R22 "Res_0603" R0603 7968.02,3909.87 r90 top
R23 "Res_0402" R0402 5118.21,5175.45 r0 top
R24 "Res_0402" R0402 5119.47,5271.49 r0 top
R26 "Res_0402" R0402 5120.05,5374.48 r0 top
R27 "Res_0402" R0402 5119.47,5481.49 r0 top
R30 "Res_0402" R0402 5894.23,7743.5 r270 top
R31 "Res_0402" R0402 5938.6,7743.5 r270 top
R33 "Res_0402" R0402 5982.98,7743.5 r270 top
R35 "Res_0402" R0402 6027.35,7743.5 r270 top
R36 "Res_0402" R0402 6071.73,7743.5 r270 top
R37 "Res_0402" R0402 6116.1,7743.5 r270 top
R39 "Res_0402" R0402 6160.48,7743.5 r270 top
R40 "Res_0402" R0402 5719.47,6866.49 r270 top
R41 "Res_0402" R0402 6007.18,7358.81 r270 top
R42 "Res_0402" R0402 6204.85,7743.5 r270 top
R45 "Res_0402" R0402 6249.23,7743.5 r270 top
R46 "Res_0603" R0603 6299.23,7729.21 r270 top
R47 "Res_0402" R0402 6533.52,7760.56 r270 top
R48 "Res_0402" R0402 6483.52,7760.56 r90 top
R49 "Res_0402" R0402 6779.47,3589.38 r270 top
R50 "Res_0402" R0402 4812.43,3309.45 r90 top
R51 "Res_0402" R0402 6734.47,3511.49 r270 top
R52 "Res_0402" R0402 4919.47,3656.49 r0 top
R53 "Res_0402" R0402 6779.47,3511.49 r90 top
R54 "Res_0402" R0402 4724.47,3331.49 r180 top
R55 "Res_0402" R0402 6735.17,3589.38 r270 top
R56 "Res_0402" R0402 4724.47,3421.49 r0 top
R57 "Res_0402" R0402 4724.47,3291.49 r180 top
R58 "Res_0603" R0603 7241.08,6240.28 r0 bottom
R59 "Res_0402" R0402 7309.47,6021.49 r90 bottom
R60 "Res_0603" R0603 7239.47,6306.49 r0 bottom
R61 "Res_0603" R0603 7226.25,6006.99 r0 bottom
R62 "Res_0603" R0603 4988.59,4362.31 r180 bottom
R63 "Res_0603" R0603 7109.47,6066.49 r0 bottom
R64 "Res_0603" R0603 4859.47,4516.49 r0 bottom
R65 "Res_0603" R0603 4988.59,4422.31 r180 bottom
R66 "Res_0603" R0603 4774.47,4486.49 r270 bottom
R69 "Res_0603" R0603 4670.01,4556.8 r0 top
R70 "Res_0603" R0603 4670.01,4616.8 r180 top
R71 "Res_0603" R0603 4790.01,4616.8 r0 top
R72 "Res_0603" R0603 4890.01,4461.8 r270 top
R73 "Res_0603" R0603 4985.01,4346.8 r180 top
R84 "Res_0603" R0603 7803.92,5012.24 r90 top
R85 "Res_0603" R0603 7479.47,4961.49 r270 top
R86 "Res_0603" R0603 7964.47,5621.49 r180 top
R87 "Res_0603" R0603 8249.47,5586.49 r90 top
R88 "Res_0603" R0603 8193.3,5586.92 r270 top
R89 "Res_0603" R0603 7964.47,5566.49 r0 top
R90 "Res_0603" R0603 7864.47,5012.24 r90 top
R91 "Res_0603" R0603 8104.47,5616.49 r0 top
R92 "Res_0603" R0603 7664.43,5085.04 r270 top
R93 "Res_0603" R0603 7839.77,5319.7 r270 top
R94 "Res_0603" R0603 7727.76,5861.2 r270 top
R95 "Res_0603" R0603 7632.42,5780.86 r180 top
R96 "Res_0603" R0603 7632.76,6001.2 r180 top
R97 "Res_0603" R0603 7787.76,5861.2 r270 top
R98 "Res_0603" R0603 7254.47,6531.49 r270 bottom
R99 "Res_0603" R0603 7632.76,5941.2 r0 top
R100 "Res_0603" R0603 7099.14,6530.93 r270 bottom
R101 "Res_0603" R0603 7659.43,5320.04 r270 top
R102 "Res_0603" R0603 7199.14,6530.93 r90 bottom
R103 "Res_0603" R0603 7407.76,5861.2 r90 top
R104 "Res_0603" R0603 7497.76,5941.2 r0 top
R105 "Res_0603" R0603 7496.9,6003.39 r0 top
R106 "Res_0603" R0603 7499.47,5691.49 r180 top
R107 "Res_0603" R0603 7502.76,5781.2 r180 top
R367 "Res_0402" R0402 6739.94,7251.46 r90 top
R368 "Res_0402" R0402 6791.51,7251.01 r90 top
R369 "Res_0402" R0402 6843.07,7251.46 r90 top
R370 "Res_0402" R0402 6636.82,7252.71 r270 top
R371 "Res_0402" R0402 6688.38,7252.71 r270 top
R374 "25121WF390MT4E" r2512 7549.47,4446.49 r180 top
R375 "25121WF390MT4E" r2512 8284.47,4716.49 r90 top
R376 "Res_0402" R0402 4861.43,3966.49 r90 top
R377 "Res_0402" R0402 4904.47,3966.49 r270 top
R378 "Res_0402" R0402 4906.7,4049.24 r90 top
R379 "Res_0402" R0402 4952.22,4049.26 r90 top
R380 "Res_0402" R0402 4861.57,4049.05 r270 top
R381 "Res_0402" R0402 4598.64,3952.01 r180 top
R382 "Res_0402" R0402 4599.47,3996.49 r180 top
R383 "Res_0402" R0402 4304.47,3699.41 r180 top
R384 "Res_0402" R0402 4222.28,3699.41 r180 top
R385 "Res_0603" R0603 7729.47,4926.49 r180 top
R386 "Res_0603" R0603 8159.79,5542.68 r90 bottom
R387 "Res_0603" R0603 8219.79,5542.68 r90 bottom
R388 "Res_0402" R0402 6034.47,6856.49 r270 top
RX "Test-Point" Test-Point-0.5mm 6354.84,7326.67 r180 bottom
SW1 "MK-14C01-G2" SW-SMD_DEALON_MK-14C01-G2 8029.47,3216.49 r0 top
TP1 "Test-Point" Test-Point-0.5mm 5344.47,6141.49 r180 top
TP2 "Test-Point" Test-Point-0.5mm 5344.47,6231.49 r0 top
TP3 "Test-Point" Test-Point-0.5mm 7031.48,5423.49 r0 top
TP4 "Test-Point" Test-Point-0.5mm 7031.48,5482.86 r0 top
TX "Test-Point" Test-Point-0.5mm 6409.84,7326.04 r180 bottom
U1 "RU3030M3" V-DFN3333-8_L3.3-W3.3-P0.65-BL 7474.04,4614.39 r90 top
U3 "RU3030M3" V-DFN3333-8_L3.3-W3.3-P0.65-BL 8059.47,4626.49 r270 top
U4 "RU3030M3" V-DFN3333-8_L3.3-W3.3-P0.65-BL 7474.01,4761.02 r270 top
U5 "RU3030M3" V-DFN3333-8_L3.3-W3.3-P0.65-BL 8055.81,4769.03 r90 top
U6 "100uF贴片电解" CAP-SMD_BD6.3-L6.6-W6.6-LS7.4-FD 8094.47,5001.49 r180 top
U7 "100uF贴片电解" CAP-SMD_BD6.3-L6.6-W6.6-LS7.4-FD 7524.47,4221.49 r180 top
U8 "IP2363" QFN-32_L5.0-W5.0-P0.50-BL-EP3.7 8095.5,4178.09 r90 top
U9 "dualLED-红绿双色LED" LED-SMD_4P-L1.6-W1.5 7724.47,3211.49 r180 top
U10 "E32-400M30S" WIRELM-SMD_E32-400M30S 4549.47,5436.49 r180 top
U11 "1.25mm_6p_卧式i贴片" CONN-SMD_6P-P1.25_HC-1.25-6PWT 5124.47,7776.49 r270 top
U12 "1.25mm_6p_卧式i贴片" CONN-SMD_6P-P1.25_HC-1.25-6PWT 7174.47,7776.49 r90 top
U13 "1.25mm_6p_卧式i贴片" CONN-SMD_6P-P1.25_HC-1.25-6PWT 5589.47,7921.49 r180 top
U14 "1.25mm_6p_卧式i贴片" CONN-SMD_6P-P1.25_HC-1.25-6PWT 6714.47,7921.49 r180 top
U16 "LM1117-5V" SOT-89-3_L4.5-W2.5-P1.50-LS4.1-BR 6089.47,6611.49 r270 top
U17 "LM1117-5V" SOT-89-3_L4.5-W2.5-P1.50-LS4.1-BR 6499.47,7541.49 r0 top
U18 "按键" SW-SMD_4P-L6.0-W6.0-P4.50-LS9.0-2 5289.47,7001.49 r180 bottom
U19 "ESP32-S3" QFN-56_L7.0-W7.0-P0.40-TL-EP4.0 6143.82,7122.15 r0 top
U21 "W25Q128JVSIQ" SOIC-8_L5.3-W5.3-P1.27-LS8.0-BL 6524.47,7091.49 r90 top
U24 "ESD" ESD 9034.47,4686.49 r90 top
U25 "IPEX天线座,(贴片),特征阻抗50Ω,尺寸2.6mmx2.6mmx1.25mmROHS" IPEX-SMD_HC-RF-IPEX0303-01 5599.47,7511.49 r0 top
U30 "B5819WS" SOD-123_L2.8-W1.8-LS3.7-FD 5774.47,3526.49 r270 top
U35 "SY7203DBC" DFN-10_L3.0-W3.0-P0.50-BL-EP 4750.1,4019.11 r90 top
U36 "SY8113BADC" TSOT-23-6_L2.9-W1.6-P0.95-LS2.8-BR 8099.47,5716.49 r180 top
U37 "4.7uH 3A" IND-SMD_L7.3-W7.3_GSDRH74P 8099.47,5941.49 r180 top
U38 "NB679GD-Z" QFN-12_L3.0-W2.0-P0.5-TL_NB680 7771.39,5166.24 r180 top
U72 "MCP23017T-E/ML" QFN-28_L6.0-W6.0-P0.65-BL-EP3.7 6747.82,7453.22 r270 top
U75 "按键" SW-SMD_4P-L6.0-W6.0-P4.50-LS9.0-2 7029.47,6991.49 r180 bottom
U76 "micro sd卡座" MICRO-USB-SMD_MICRO-SD 7814.47,6311.49 r0 bottom
U77 "21700" 21700 8844.47,6496.49 r0 top
U78 "21700" 21700 3489.47,3751.49 r180 top
U79 "Type-A_USB3.0_3.4mm" USB-A-SMD_TYPE-A_USB3.0_3.4MM 6249.47,3431.49 r0 top
U80 "按键" SW-SMD_4P-L6.0-W6.0-P4.50-LS9.0-2 4714.47,6591.49 r0 top
U81 "按键" SW-SMD_4P-L6.0-W6.0-P4.50-LS9.0-2 7567.01,6593.08 r0 top
U83 "PAM8302AAYCR_C4990730" U-DFN3030-8_L3.0-W3.0-P0.65-BL-EP 4369.47,3591.49 r270 top
USB1 "KH-TYPE-C-16P" USB-C-SMD_KH-TYPE-C-16P 7354.47,3278.9 r0 top
USB2 "KH-TYPE-C-16P" USB-C-SMD_KH-TYPE-C-16P 6879.27,3278.9 r0 top
USB3 "KH-HDMI-0002" HDMI-SMD_KH-HDMI-0002 5532.31,3286.49 r0 top
X1 "1N224000CC0BN" OSC-SMD_4P-L3.2-W2.5-BL_4 6117.02,7382.25 r0 top

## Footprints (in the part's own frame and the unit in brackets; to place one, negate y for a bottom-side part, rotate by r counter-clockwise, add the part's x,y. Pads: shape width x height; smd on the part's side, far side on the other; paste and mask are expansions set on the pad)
21700 [mil]
  oval 420x150 hole 60 slot 372.05 at 0 deg: 1(0,90) 2(0,-2835)
  silkscreen extent -415,-2751 412,5
AUDIO-SMD_PJ-3420-A-SMT_C319102 [mm]
  rect 1.8x2.3 smd: 1(-4.7,-3.5) 2(-4.7,3.5) 3(-1.3,-3.5) 4(2.5,3.5) 5(4.7,3.5) 6(4.2,-3.5)
  Board Outline Layer circle w0.005: c2.7,0 r0.6
  Board Outline Layer circle w0.005: c-4.3,0 r0.6
  Board Outline Layer circle w0.254: c2.7,0 r0.6
  Board Outline Layer circle w0.254: c-4.3,0 r0.6
  Multi-Layer board cut-out: 2.7,-0.6 2.997,-0.517 3.214,-0.298 3.293,0 3.214,0.298 2.997,0.517 2.7,0.6 2.7,0.6 2.403,0.517 2.186,0.298 2.107,0 2.186,-0.298 2.403,-0.517 2.7,-0.6
  Multi-Layer board cut-out: -4.3,-0.6 -4.003,-0.517 -3.786,-0.298 -3.707,0 -3.786,0.298 -4.003,0.517 -4.3,0.6 -4.3,0.6 -4.597,0.517 -4.814,0.298 -4.893,0 -4.814,-0.298 -4.597,-0.517 -4.3,-0.6
  silkscreen extent -8.8,-3.3 5.77,3.3
C0402 [mm]
  rect 0.79x0.54 smd: 1(-0.545,0) 2(0.545,0)
  silkscreen extent -1.17,-0.5 1.17,0.5
C0603 [mm]
  rect 0.8x0.9 smd: 1(-0.7,0) 2(0.7,0)
  silkscreen extent -1.41,-0.71 1.39,0.72
C0805 [mm]
  rect 1.41x1.35 smd: 1(-1.03,0) 2(1.03,0)
  silkscreen extent -1.96,-0.9 1.96,0.9
CAP-SMD_BD5.0-L5.3-W5.3-LS6.0-FD [mm]
  rect 2.8x1.1 smd: 1(-2.1,0) 2(2.1,0)
  silkscreen extent -2.66,-2.62 2.66,2.65
CAP-SMD_BD6.3-L6.6-W6.6-LS7.4-FD [mm]
  rect 3.5x1.2 smd: 1(-2.67,0) 2(2.67,0)
  silkscreen extent -3.38,-3.38 3.38,3.38
CONN-SMD_2P-P2.50-WT [mm]
  rect 1.3x2.5 smd: 1(-1.25,4.25)
  rect 1.3x4 smd: 2(1.25,3.5)
  rect 1.9x4 smd: 3(4.5,-3.5) 4(-4.5,-3.5)
  silkscreen extent -5.03,-5.3 5.01,4.14
CONN-SMD_4P-P1.00_TXGA_FWF10002-S04S24W5M [mm]
  rect 0.7x1.6 smd: 1(-1.5,1.25) 2(-0.5,1.25) 3(0.5,1.25) 4(1.5,1.25)
  rect 1x1.4 smd: 5(2.8,-1.055)
  rect 1.2x1.8 smd: 6(-2.8,-1.25)
  silkscreen extent -3.25,-1.94 3.25,1.16
CONN-SMD_6P-P1.25_HC-1.25-6PWT [mm]
  rect 0.8x2.2 smd: 1(-3.125,1.3) 2(-1.875,1.3) 3(-0.625,1.3) 4(0.625,1.3) 5(1.875,1.3) 6(3.125,1.3)
  rect 2.35x2.5 smd: 7(-5.505,-1.3) 8(5.505,-1.3)
  silkscreen extent -6.33,-3.56 6.35,1.88
conn-smd_df40hc-3.0-100ds-0.4v-51#1 [mm]
  rect 0.2x1.14 smd: 1(10.595,1.2) 2(10.595,-1.46) 3(10.195,1.2) 4(10.195,-1.46) 5(9.795,1.2) 6(9.795,-1.46) 7(9.395,1.2) 8(9.395,-1.46) 9(8.995,1.2) 10(8.995,-1.46) 11(8.595,1.2) 12(8.595,-1.46) 13(8.195,1.2) 14(8.195,-1.46) 15(7.795,1.2) 16(7.795,-1.46) 17(7.395,1.2) 18(7.395,-1.46) 19(6.995,1.2) 20(6.995,-1.46) 21(6.595,1.2) 22(6.595,-1.46) 23(6.195,1.2) 24(6.195,-1.46) 25(5.795,1.2) 26(5.795,-1.46) 27(5.395,1.2) 28(5.395,-1.46) 29(4.995,1.2) 30(4.995,-1.46) 31(4.595,1.2) 32(4.595,-1.46) 33(4.195,1.2) 34(4.195,-1.46) 35(3.795,1.2) 36(3.795,-1.46) 37(3.395,1.2) 38(3.395,-1.46) 39(2.995,1.2) 40(2.995,-1.46) 41(2.595,1.2) 42(2.595,-1.46) 43(2.195,1.2) 44(2.195,-1.46) 45(1.795,1.2) 46(1.795,-1.46) 47(1.395,1.2) 48(1.395,-1.46) 49(0.995,1.2) 50(0.995,-1.46) 51(0.595,1.2) 52(0.595,-1.46) 53(0.195,1.2) 54(0.195,-1.46) 55(-0.205,1.2) 56(-0.205,-1.46) 57(-0.605,1.2) 58(-0.605,-1.46) 59(-1.005,1.2) 60(-1.005,-1.46) 61(-1.405,1.2) 62(-1.405,-1.46) 63(-1.805,1.2) 64(-1.805,-1.46) 65(-2.205,1.2) 66(-2.205,-1.46) 67(-2.605,1.2) 68(-2.605,-1.46) 69(-3.005,1.2) 70(-3.005,-1.46) 71(-3.405,1.2) 72(-3.405,-1.46) 73(-3.805,1.2) 74(-3.805,-1.46) 75(-4.205,1.2) 76(-4.205,-1.46) 77(-4.605,1.2) 78(-4.605,-1.46) 79(-5.005,1.2) 80(-5.005,-1.46) 81(-5.405,1.2) 82(-5.405,-1.46) 83(-5.805,1.2) 84(-5.805,-1.46) 85(-6.205,1.2) 86(-6.205,-1.46) 87(-6.605,1.2) 88(-6.605,-1.46) 89(-7.005,1.2) 90(-7.005,-1.46) 91(-7.405,1.2) 92(-7.405,-1.46) 93(-7.805,1.2) 94(-7.805,-1.46) 95(-8.205,1.2) 96(-8.205,-1.46) 97(-8.605,1.2) 98(-8.605,-1.46) 99(-9.005,1.2) 100(-9.005,-1.46)
  silkscreen extent -9.98,-1.55 11.55,1.29
conn-smd_df40hc-3.0-100ds-0.4v-51#2 [mm]
  rect 0.2x1.14 smd: 1(-9.482,1.274) 2(-9.482,-1.366) 3(-9.082,1.274) 4(-9.082,-1.366) 5(-8.682,1.274) 6(-8.682,-1.366) 7(-8.282,1.274) 8(-8.282,-1.366) 9(-7.882,1.274) 10(-7.882,-1.366) 11(-7.482,1.274) 12(-7.482,-1.366) 13(-7.082,1.274) 14(-7.082,-1.366) 15(-6.682,1.274) 16(-6.682,-1.366) 17(-6.282,1.274) 18(-6.282,-1.366) 19(-5.882,1.274) 20(-5.882,-1.366) 21(-5.482,1.274) 22(-5.482,-1.366) 23(-5.082,1.274) 24(-5.082,-1.366) 25(-4.682,1.274) 26(-4.682,-1.366) 27(-4.282,1.274) 28(-4.282,-1.366) 29(-3.882,1.274) 30(-3.882,-1.366) 31(-3.482,1.274) 32(-3.482,-1.366) 33(-3.082,1.274) 34(-3.082,-1.366) 35(-2.682,1.274) 36(-2.682,-1.366) 37(-2.282,1.274) 38(-2.282,-1.366) 39(-1.882,1.274) 40(-1.882,-1.366) 41(-1.482,1.274) 42(-1.482,-1.366) 43(-1.082,1.274) 44(-1.082,-1.366) 45(-0.682,1.274) 46(-0.682,-1.366) 47(-0.282,1.274) 48(-0.282,-1.366) 49(0.118,1.274) 50(0.118,-1.366) 51(0.518,1.274) 52(0.518,-1.366) 53(0.918,1.274) 54(0.918,-1.366) 55(1.318,1.274) 56(1.318,-1.366) 57(1.718,1.274) 58(1.718,-1.366) 59(2.118,1.274) 60(2.118,-1.366) 61(2.518,1.274) 62(2.518,-1.366) 63(2.918,1.274) 64(2.918,-1.366) 65(3.318,1.274) 66(3.318,-1.366) 67(3.718,1.274) 68(3.718,-1.366) 69(4.118,1.274) 70(4.118,-1.366) 71(4.518,1.274) 72(4.518,-1.366) 73(4.918,1.274) 74(4.918,-1.366) 75(5.318,1.274) 76(5.318,-1.366) 77(5.718,1.274) 78(5.718,-1.366) 79(6.118,1.274) 80(6.118,-1.366) 81(6.518,1.274) 82(6.518,-1.366) 83(6.918,1.274) 84(6.918,-1.366) 85(7.318,1.274) 86(7.318,-1.366) 87(7.718,1.274) 88(7.718,-1.366) 89(8.118,1.274) 90(8.118,-1.366) 91(8.518,1.274) 92(8.518,-1.366) 93(8.918,1.274) 94(8.918,-1.366) 95(9.318,1.274) 96(9.318,-1.366) 97(9.718,1.274) 98(9.718,-1.366) 99(10.118,1.274) 100(10.118,-1.366)
  silkscreen extent -10.99,-1.46 11.56,1.38
CONN-SMD_DF40HC-3.0-100DS-0.4V-51 [mm]
  rect 0.2x1.14 smd: 1(10.39,1.27) 2(10.39,-1.39) 3(9.99,1.27) 4(9.99,-1.39) 5(9.59,1.27) 6(9.59,-1.39) 7(9.19,1.27) 8(9.19,-1.39) 9(8.79,1.27) 10(8.79,-1.39) 11(8.39,1.27) 12(8.39,-1.39) 13(7.99,1.27) 14(7.99,-1.39) 15(7.59,1.27) 16(7.59,-1.39) 17(7.19,1.27) 18(7.19,-1.39) 19(6.79,1.27) 20(6.79,-1.39) 21(6.39,1.27) 22(6.39,-1.39) 23(5.99,1.27) 24(5.99,-1.39) 25(5.59,1.27) 26(5.59,-1.39) 27(5.19,1.27) 28(5.19,-1.39) 29(4.79,1.27) 30(4.79,-1.39) 31(4.39,1.27) 32(4.39,-1.39) 33(3.99,1.27) 34(3.99,-1.39) 35(3.59,1.27) 36(3.59,-1.39) 37(3.19,1.27) 38(3.19,-1.39) 39(2.79,1.27) 40(2.79,-1.39) 41(2.39,1.27) 42(2.39,-1.39) 43(1.99,1.27) 44(1.99,-1.39) 45(1.59,1.27) 46(1.59,-1.39) 47(1.19,1.27) 48(1.19,-1.39) 49(0.79,1.27) 50(0.79,-1.39) 51(0.39,1.27) 52(0.39,-1.39) 53(-0.01,1.27) 54(-0.01,-1.39) 55(-0.41,1.27) 56(-0.41,-1.39) 57(-0.81,1.27) 58(-0.81,-1.39) 59(-1.21,1.27) 60(-1.21,-1.39) 61(-1.61,1.27) 62(-1.61,-1.39) 63(-2.01,1.27) 64(-2.01,-1.39) 65(-2.41,1.27) 66(-2.41,-1.39) 67(-2.81,1.27) 68(-2.81,-1.39) 69(-3.21,1.27) 70(-3.21,-1.39) 71(-3.61,1.27) 72(-3.61,-1.39) 73(-4.01,1.27) 74(-4.01,-1.39) 75(-4.41,1.27) 76(-4.41,-1.39) 77(-4.81,1.27) 78(-4.81,-1.39) 79(-5.21,1.27) 80(-5.21,-1.39) 81(-5.61,1.27) 82(-5.61,-1.39) 83(-6.01,1.27) 84(-6.01,-1.39) 85(-6.41,1.27) 86(-6.41,-1.39) 87(-6.81,1.27) 88(-6.81,-1.39) 89(-7.21,1.27) 90(-7.21,-1.39) 91(-7.61,1.27) 92(-7.61,-1.39) 93(-8.01,1.27) 94(-8.01,-1.39) 95(-8.41,1.27) 96(-8.41,-1.39) 97(-8.81,1.27) 98(-8.81,-1.39) 99(-9.21,1.27) 100(-9.21,-1.39)
  silkscreen extent -10.18,-1.48 11.35,1.36
DFN2510-10_L2.5-W1.0-P0.50-BL [mm]
  rect 0.2x0.665 smd: 1(-1,-0.433) 2(-0.5,-0.433) 4(0.5,-0.433) 5(1,-0.433) 6(1,0.433) 7(0.5,0.433) 9(-0.5,0.433) 10(-1,0.433)
  rect 0.4x0.665 smd: 3(0,-0.433) 8(0,0.433)
  silkscreen extent -1.33,-1.11 1.33,0.58
DFN-10_L3.0-W3.0-P0.50-BL-EP [mm]
  rect 0.25x0.65 smd: 1(-1,-1.411) 2(-0.5,-1.411) 3(0,-1.411) 4(0.5,-1.411) 5(1,-1.411) 6(1,1.411) 7(0.5,1.411) 8(0,1.411) 9(-0.5,1.411) 10(-1,1.411)
  rect 2x1.2 smd: 11(0,0)
  silkscreen extent -1.58,-2.1 1.58,1.58
ESD [mil]
  silkscreen extent -130,-114 141,133
FPC-SMD_15P-P0.50_GT-F0512SR18-15S0101 [mm]
  rect 0.3x1.3 smd: 1(-3.5,1.625) 2(-3,1.625) 3(-2.5,1.625) 4(-2,1.625) 5(-1.5,1.625) 6(-1,1.625) 7(-0.5,1.625) 8(0,1.625) 9(0.5,1.625) 10(1,1.625) 11(1.5,1.625) 12(2,1.625) 13(2.5,1.625) 14(3,1.625) 15(3.5,1.625)
  rect 1.9x2.2 smd: 16(5.45,-1.625) 17(-5.45,-1.625)
  silkscreen extent -5.85,-3.7 5.85,1.3
FPC-SMD_P0.50-6P_AFC01-S06FCA-00 [mm]
  rect 0.3x1.3 smd: 1(-1.248,1.339) 2(-0.748,1.339) 3(-0.248,1.339) 4(0.252,1.339) 5(0.752,1.339) 6(1.252,1.339)
  rect 2x1.6 smd: 7(-2.95,-1.339) 8(2.95,-1.339)
  silkscreen extent -3.72,-4.36 3.7,1.75
HDMI-SMD_KH-HDMI-0002 [mm]
  rect 0.2x1.2 smd: 1(3.6,2.86) 2(3.2,2.86) 3(2.8,2.86) 4(2.4,2.86) 5(2,2.86) 6(1.6,2.86) 7(1.2,2.86) 8(0.8,2.86) 9(0.4,2.86) 10(0,2.86) 11(-0.4,2.86) 12(-0.8,2.86) 13(-1.2,2.86) 14(-1.6,2.86) 15(-2,2.86) 16(-2.4,2.86) 17(-2.8,2.86) 18(-3.2,2.86) 19(-3.6,2.86)
  rect 1.38x1.4 smd: 20(-6.35,1.64) 20(6.35,1.64) 21(-6.35,-2.86) 21(6.35,-2.86)
  Board Outline Layer circle w0.005: c3.75,0.84 r0.5
  Board Outline Layer circle w0.005: c-3.75,0.84 r0.5
  Board Outline Layer circle w0.254: c3.75,0.84 r0.5
  Board Outline Layer circle w0.254: c-3.75,0.84 r0.5
  Multi-Layer board cut-out: 4.25,0.84 4.2,1.057 4.062,1.231 3.861,1.327 3.638,1.327 3.438,1.231 3.299,1.057 3.25,0.84 3.25,0.84 3.299,0.623 3.438,0.449 3.639,0.352 3.861,0.352 4.062,0.449 4.2,0.623 4.25,0.84
  Multi-Layer board cut-out: -3.25,0.84 -3.3,1.057 -3.438,1.231 -3.639,1.327 -3.861,1.327 -4.062,1.231 -4.201,1.057 -4.25,0.84 -4.25,0.84 -4.201,0.623 -4.062,0.449 -3.861,0.352 -3.639,0.352 -3.438,0.449 -3.3,0.623 -3.25,0.84
  silkscreen extent -5.6,-4.89 5.6,3.11
IND-SMD_L4.0-W4.0_LQH44PN2R2MP0L [mm]
  rect 1.5x4 smd: 1(-1.8,0) 2(1.8,0)
  silkscreen extent -2,-2.25 2,2.25
IND-SMD_L5.4-W5.1_SPM5020 [mm]
  rect 1.4x2.8 smd: 1(-2.2,0) 2(2.2,0)
  silkscreen extent -2.7,-2.55 2.7,2.6
IND-SMD_L7.3-W7.3_GSDRH74P [mm]
  rect 1.8x2.5 smd: 1(-3.1,0) 2(3.1,0)
  silkscreen extent -3.65,-3.65 3.65,3.65
IND-SMD_L8.0-W8.0 [mm]
  rect 3.024x7.5 smd: 1(3.328,0) 2(-3.328,0)
  silkscreen extent -4.08,-4.02 4.08,4.02
IPEX-SMD_HC-RF-IPEX0303-01 [mm]
  rect 1x1.05 smd: 1(0,-1.5) 4(0,1.5)
  rect 1.05x2.2 smd: 2(1.475,0) 3(-1.475,0)
  silkscreen extent -1.45,-1.45 1.45,1.45
Key_SMD_3x4x2 [mm]
  rect 1.53x1.36 smd: 1(-2.035,0) 2(2.035,0)
  silkscreen extent -2.08,-1.58 2.08,1.58
L0402 [mm]
  rect 0.79x0.54 smd: 1(-0.545,0) 2(0.545,0)
  silkscreen extent -1.17,-0.5 1.17,0.5
L0603 [mm]
  rect 0.8x0.864 smd: 1(-0.7,0) 2(0.7,0)
  silkscreen extent -1.42,-0.65 1.41,0.67
L1206 [mm]
  rect 1.485x1.728 smd: 1(-1.593,0) 2(1.593,0)
  silkscreen extent -2.56,-1.09 2.56,1.09
LED-SMD_4P-L1.6-W1.5 [mm]
  rect 0.75x0.65 smd: 1(0.5,0.725) 2(0.5,-0.725) 3(-0.5,-0.725) 4(-0.5,0.725)
  silkscreen extent -0.89,-0.17 0.89,0.2
MICRO-USB-SMD_MICRO-SD [mm]
  rect 0.7x1.6 smd: 1(2.25,5.2) 2(1.15,5.2) 3(0.05,5.2) 4(-1.05,5.2) 5(-2.15,5.2) 6(-3.25,5.2) 7(-4.35,5.2) 8(-5.45,5.2) CD(-6.55,5.2)
  rect 1.2x1.2 smd: G1(-7.75,4.3) G4(6.85,4.3)
  rect 1.2x2.2 smd: G2(-7.75,-5.2) G3(7.75,-5.2)
  round 1.524 hole 1: G3(-4.95,-5.7) G3(3.05,-5.7)
  silkscreen extent -7.35,-9.7 7.35,6.48
OK-06F024-04 [mm]
  rect 0.23x0.92 smd: 1(-4.4,0) 2(-4,0) 3(-3.6,0) 4(-3.2,0) 5(-2.8,0) 6(-2.4,0) 7(-2,0) 8(-1.6,0) 9(-1.2,0) 10(-0.8,0) 11(-0.4,0) 12(0,0) 13(0,3.28) 14(-0.4,3.28) 15(-0.8,3.28) 16(-1.2,3.28) 17(-1.6,3.28) 18(-2,3.28) 19(-2.4,3.28) 20(-2.8,3.28) 21(-3.2,3.28) 22(-3.6,3.28) 23(-4,3.28) 24(-4.4,3.28)
  rect 0.7x1.2 smd: 25(-5.3,0.14) 26(0.9,0.14) 27(0.9,3.14) 28(-5.3,3.14)
  silkscreen extent -5.84,-1.26 1.44,3.94
OSC-SMD_4P-L3.2-W2.5-BL_4 [mm]
  rect 1.4x1.2 smd: 1(-1.1,-0.875) 2(1.1,-0.875) 3(1.1,0.875) 4(-1.1,0.875)
  silkscreen extent -2.29,-1.9 2.03,1.65
QFN-12_L3.0-W2.0-P0.5-TL_NB680 [mm]
  oval 1.5x0.3 smd: 1(-0.65,0.5) 2(-0.65,-0.5) 7(0.45,0)
  oval 0.25x0.7 smd: 3(-0.85,-1.45) 4(-0.35,-1.45) 5(0.15,-1.45) 6(0.65,-1.45) 9(0.65,1.45) 10(0.15,1.45) 11(-0.35,1.45) 12(-0.85,1.45)
  oval 0.7x0.25 smd: 8(0.85,0.5)
  silkscreen extent -1.65,-1.65 1.05,1.65
QFN-28_L6.0-W6.0-P0.65-BL-EP3.7 [mm]
  oval 0.364x1.055 smd: 1(-1.95,-2.878) 2(-1.3,-2.878) 3(-0.65,-2.878) 4(0,-2.878) 5(0.65,-2.878) 6(1.3,-2.878) 7(1.95,-2.878) 15(1.95,2.878) 16(1.3,2.878) 17(0.65,2.878) 18(0,2.878) 19(-0.65,2.878) 20(-1.3,2.878) 21(-1.95,2.878)
  oval 1.055x0.364 smd: 8(2.878,-1.95) 9(2.878,-1.3) 10(2.878,-0.65) 11(2.878,0) 12(2.878,0.65) 13(2.878,1.3) 14(2.878,1.95) 22(-2.878,1.95) 23(-2.878,1.3) 24(-2.878,0.65) 25(-2.878,0) 26(-2.878,-0.65) 27(-2.878,-1.3) 28(-2.878,-1.95)
  rect 3.7x3.7 smd: 29(0,0)
  silkscreen extent -3.08,-3.53 3.08,3.08
QFN-32_L5.0-W5.0-P0.50-BL-EP3.7 [mm]
  oval 0.28x0.9 smd: 1(-1.75,-2.55) 2(-1.25,-2.55) 3(-0.749,-2.55) 4(-0.249,-2.55) 5(0.249,-2.55) 6(0.749,-2.55) 7(1.25,-2.55) 8(1.75,-2.55) 17(1.75,2.55) 18(1.25,2.55) 19(0.749,2.55) 20(0.249,2.55) 21(-0.249,2.55) 22(-0.749,2.55) 23(-1.25,2.55) 24(-1.75,2.55)
  oval 0.9x0.28 smd: 9(2.55,-1.75) 10(2.55,-1.25) 11(2.55,-0.749) 12(2.55,-0.249) 13(2.55,0.249) 14(2.55,0.749) 15(2.55,1.25) 16(2.55,1.75) 25(-2.55,1.75) 26(-2.55,1.25) 27(-2.55,0.749) 28(-2.55,0.249) 29(-2.55,-0.249) 30(-2.55,-0.749) 31(-2.55,-1.25) 32(-2.55,-1.75)
  rect 3.7x3.7 smd: 33(0,0)
  silkscreen extent -2.7,-3.35 2.7,2.7
QFN-56_L7.0-W7.0-P0.40-TL-EP4.0 [mm]
  rect 0.665x0.2 smd: 1(-3.408,2.6) 2(-3.408,2.2) 3(-3.408,1.8) 4(-3.408,1.4) 5(-3.408,1) 6(-3.408,0.6) 7(-3.408,0.2) 8(-3.408,-0.2) 9(-3.408,-0.6) 10(-3.408,-1) 11(-3.408,-1.4) 12(-3.408,-1.8) 13(-3.408,-2.2) 14(-3.408,-2.6) 29(3.408,-2.6) 30(3.408,-2.2) 31(3.408,-1.8) 32(3.408,-1.4) 33(3.408,-1) 34(3.408,-0.6) 35(3.408,-0.2) 36(3.408,0.2) 37(3.408,0.6) 38(3.408,1) 39(3.408,1.4) 40(3.408,1.8) 41(3.408,2.2) 42(3.408,2.6)
  rect 0.2x0.665 smd: 15(-2.6,-3.408) 16(-2.2,-3.408) 17(-1.8,-3.408) 18(-1.4,-3.408) 19(-1,-3.408) 20(-0.6,-3.408) 21(-0.2,-3.408) 22(0.2,-3.408) 23(0.6,-3.408) 24(1,-3.408) 25(1.4,-3.408) 26(1.8,-3.408) 27(2.2,-3.408) 28(2.6,-3.408) 43(2.6,3.408) 44(2.2,3.408) 45(1.8,3.408) 46(1.4,3.408) 47(1,3.408) 48(0.6,3.408) 49(0.2,3.408) 50(-0.2,3.408) 51(-0.6,3.408) 52(-1,3.408) 53(-1.4,3.408) 54(-1.8,3.408) 55(-2.2,3.408) 56(-2.6,3.408)
  rect 4x4 smd: 57(0,0)
  silkscreen extent -4.11,-3.58 3.58,3.58
R0402 [mm]
  rect 0.566x0.54 smd: 1(-0.433,0) 2(0.433,0)
  silkscreen extent -0.94,-0.5 0.94,0.5
R0603 [mil]
  rect 31.75x34.02 smd: 1(-29.66,0) 2(29.66,0)
  silkscreen extent -55,-26 55,26
R1206 [mil]
  rect 47.54x66.97 smd: 1(-58.22,0) 2(58.22,0)
  silkscreen extent -91,-42 91,42
r2512 [mil]
  rect 50.49x136.06 smd: 1(-120.72,0) 2(120.72,0)
  silkscreen extent -155,-77 155,77
S8050_SOT-23 [mm]
  rect 1x0.8 smd: 1(1.15,-0.823) 2(1.15,1.077) 3(-1.15,0.127)
  silkscreen extent -0.7,-1.37 0.7,1.63
S8550P_SOT [mil]
  rect 49.2x27.6 smd: 1(50.84,-37.4) 2(50.84,37.4) 3(-47.56,0)
  silkscreen extent -24,-58 37,58
SMA_L4.3-W2.6-LS5.2-RD [mm]
  rect 2x2 smd: 1(-2.2,0) 2(2.2,0)
  silkscreen extent -2.98,-1.5 2.6,1.5
SOD-123_L2.8-W1.8-LS3.7-FD [mm]
  rect 1.2x1.4 smd: 1(-1.7,0) 2(1.7,0)
  silkscreen extent -1.5,-1 1.5,1
SOD-523_L1.2-W0.8-LS1.6-BI [mm]
  rect 0.6x0.4 smd: 1(-0.75,0) 2(0.75,0)
  silkscreen extent -0.65,-0.5 0.65,0.5
SOIC-8_L5.3-W5.3-P1.27-LS8.0-BL [mm]
  oval 0.63x2.25 smd: 1(-1.905,-3.53) 2(-0.635,-3.53) 3(0.635,-3.53) 4(1.905,-3.53) 5(1.905,3.53) 6(0.635,3.53) 7(-0.635,3.53) 8(-1.905,3.53)
  silkscreen extent -2.82,-3.68 2.64,2.18
SOT-23-3_L2.9-W1.3-P1.90-LS2.4-BR [mm]
  rect 1.25x0.7 smd: 1(1,-0.95) 2(1,0.95) 3(-1,0)
  silkscreen extent -0.73,-1.53 0.73,1.53
SOT-23-3_L2.9-W1.6-P1.90-LS2.8-BR [mm]
  rect 1.07x0.6 smd: 1(1.235,-0.95) 2(1.235,0.95) 3(-1.235,0)
  silkscreen extent -0.88,-1.54 0.88,1.54
SOT-23-3_L3.0-W1.7-P0.95-LS2.9-BR [mil]
  rect 40.85x20.95 smd: 1(43.36,-37.4) 2(43.36,37.4) 3(-43.36,0)
  silkscreen extent -34,-60 34,60
SOT-89-3_L4.5-W2.5-P1.50-LS4.1-BR [mm]
  oval 1.9x0.7 smd: 1(1.25,-1.501) 3(1.25,1.501)
  oval 3.5x2 smd: 2(-1.25,0)
  oval 2.1x0.7 smd: 2(1.151,0)
  silkscreen extent -1.85,-2.61 1.68,2.3
SOT-323-3_L2.0-W1.3-P1.30-LS2.1-BR [mm]
  rect 0.936x0.5 smd: 1(0.898,-0.65) 2(0.898,0.65) 3(-0.898,0)
  silkscreen extent -0.7,-1.13 0.7,1.13
SW-SMD_4P-L6.0-W6.0-P4.50-LS9.0-2 [mm]
  rect 2.3x1.5 smd: 1(-4.55,2.25) 2(4.55,2.25) 3(-4.55,-2.25) 4(4.55,-2.25)
  silkscreen extent -3,-3 3,3
SW-SMD_DEALON_MK-14C01-G2 [mm]
  rect 0.9x1.2 smd: 1(-3.75,1.5) 2(-2.25,1.5) 3(-0.75,1.5) 4(0.75,1.5) 5(2.25,1.5) 6(3.75,1.5)
  rect 1x0.9 smd: 7(6,0.7) 8(6,-1.5) 9(-6,-1.5) 10(-6,0.7)
  Board Outline Layer circle w0.005: c-2.5,-0.4 r0.45
  Board Outline Layer circle w0.005: c2.5,-0.4 r0.45
  Board Outline Layer circle w0.254: c-2.5,-0.4 r0.45
  Board Outline Layer circle w0.254: c2.5,-0.4 r0.45
  Multi-Layer board cut-out: -2.05,-0.4 -2.095,-0.205 -2.22,-0.048 -2.4,0.039 -2.6,0.039 -2.781,-0.048 -2.906,-0.205 -2.95,-0.4 -2.95,-0.4 -2.906,-0.595 -2.781,-0.752 -2.6,-0.839 -2.4,-0.839 -2.22,-0.752 -2.095,-0.595 -2.05,-0.4
  Multi-Layer board cut-out: 2.95,-0.4 2.905,-0.205 2.78,-0.048 2.6,0.039 2.4,0.039 2.219,-0.048 2.094,-0.205 2.05,-0.4 2.05,-0.4 2.094,-0.595 2.219,-0.752 2.4,-0.839 2.6,-0.839 2.78,-0.752 2.905,-0.595 2.95,-0.4
  silkscreen extent -5.6,-3.81 5.6,0.9
Test-Point-0.5mm [mm]
  round 0.5 smd: 1(0,0)
test-point-0.5mm [mm]
  round 0.5 smd: 1(0,0)
TSOT-23-6_L2.9-W1.6-P0.95-LS2.8-BR [mm]
  rect 0.8x0.532 smd: 1(1.2,-0.95) 2(1.2,0) 3(1.2,0.95) 4(-1.2,0.95) 5(-1.2,0) 6(-1.2,-0.95)
  silkscreen extent -0.88,-1.82 1.44,1.53
U-DFN3030-8_L3.0-W3.0-P0.65-BL-EP [mm]
  rect 0.4x0.75 smd: 1(-0.975,-1.5) 2(-0.325,-1.5) 3(0.325,-1.5) 4(0.975,-1.5) 5(0.975,1.5) 6(0.325,1.5) 7(-0.325,1.5) 8(-0.975,1.5)
  rect 2.25x1.5 smd: 9(0,0)
  silkscreen extent -1.65,-2.33 1.65,1.65
USB-A-SMD_TYPE-A_USB3.0_3.4MM [mm]
  rect 0.45x2.2 smd: 1(-4,3.77) 2(-3,3.77) 3(-2,3.77) 4(-1,3.77) 5(0,3.77) 6(1,3.77) 7(2,3.77) 8(3,3.77) 9(4,3.77)
  oval 1.1x2.3 hole 0.61 slot 1.8 at 90 deg: 10(-6.42,3.44) 11(6.425,3.44)
  rect 1.6x1.4 smd: 12(-7.66,-5.46) 13(7.65,-5.46)
  Board Outline Layer lines w0.254: -6.6,-10.55 -6.6,1.05 ; -6.6,-10.55 -7,-10.55 -6.6,-10.55 ; -6.6,-10.55 -6.6,1.05 ; -6.6,1.05 6.6,1.05 ; -6.6,1.05 6.6,1.05 ; 6.6,-10.55 7,-10.55 6.6,-10.55 ; 6.6,-10.55 6.6,1.05 ; 6.6,-10.55 6.6,1.05
  silkscreen extent -6.7,-10.65 7.76,3.79
USB-C-SMD_KH-TYPE-C-16P [mm]
  oval 1.2x2 hole 0.7 slot 1.7 at 90 deg: 1(-4.32,1.765) 2(4.32,1.765)
  oval 1.2x1.8 hole 0.7 slot 1.4 at 90 deg: 3(-4.32,-2.415) 4(4.32,-2.415)
  rect 0.3x1.3 smd: A1(-3.35,2.415) A4(-2.55,2.415) A5(-1.25,2.415) A6(-0.25,2.415) A7(0.25,2.415) A8(1.25,2.415) A9(2.55,2.415) A12(3.35,2.415) B1(3.05,2.415) B4(2.25,2.415) B5(1.75,2.415) B6(0.75,2.415) B7(-0.75,2.415) B8(-1.75,2.415) B9(-2.25,2.415) B12(-3.05,2.415)
  Board Outline Layer circle w0.005: c-2.89,1.235 r0.35
  Board Outline Layer circle w0.005: c2.89,1.235 r0.35
  Board Outline Layer circle w0.254: c-2.89,1.235 r0.35
  Board Outline Layer circle w0.254: c2.89,1.235 r0.35
  Multi-Layer board cut-out: -2.54,1.235 -2.588,1.409 -2.716,1.535 -2.89,1.582 -3.064,1.535 -3.192,1.409 -3.24,1.235 -3.24,1.235 -3.192,1.061 -3.064,0.935 -2.89,0.888 -2.716,0.935 -2.588,1.061 -2.54,1.235
  Multi-Layer board cut-out: 3.24,1.235 3.192,1.409 3.064,1.535 2.89,1.582 2.716,1.535 2.588,1.409 2.54,1.235 2.54,1.235 2.588,1.061 2.716,0.935 2.89,0.888 3.064,0.935 3.192,1.061 3.24,1.235
  silkscreen extent -4.57,-5.08 4.57,0.57
V-DFN3333-8_L3.3-W3.3-P0.65-BL [mm]
  rect 0.42x1 smd: 1(-0.965,-1.473) 2(-0.315,-1.473) 3(0.335,-1.473) 4(0.985,-1.473)
  rect 0.42x0.65 smd: 5(0.985,1.569) 6(0.335,1.569) 7(-0.315,1.569) 8(-0.965,1.569)
  rect 2.37x1.6 smd: 8(0.004,0.328)
  silkscreen extent -1.62,-2.53 1.63,1.6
